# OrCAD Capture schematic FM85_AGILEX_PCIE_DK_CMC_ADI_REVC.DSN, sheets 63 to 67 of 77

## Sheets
63 PWR -VCC_HSSI_GXR: size C
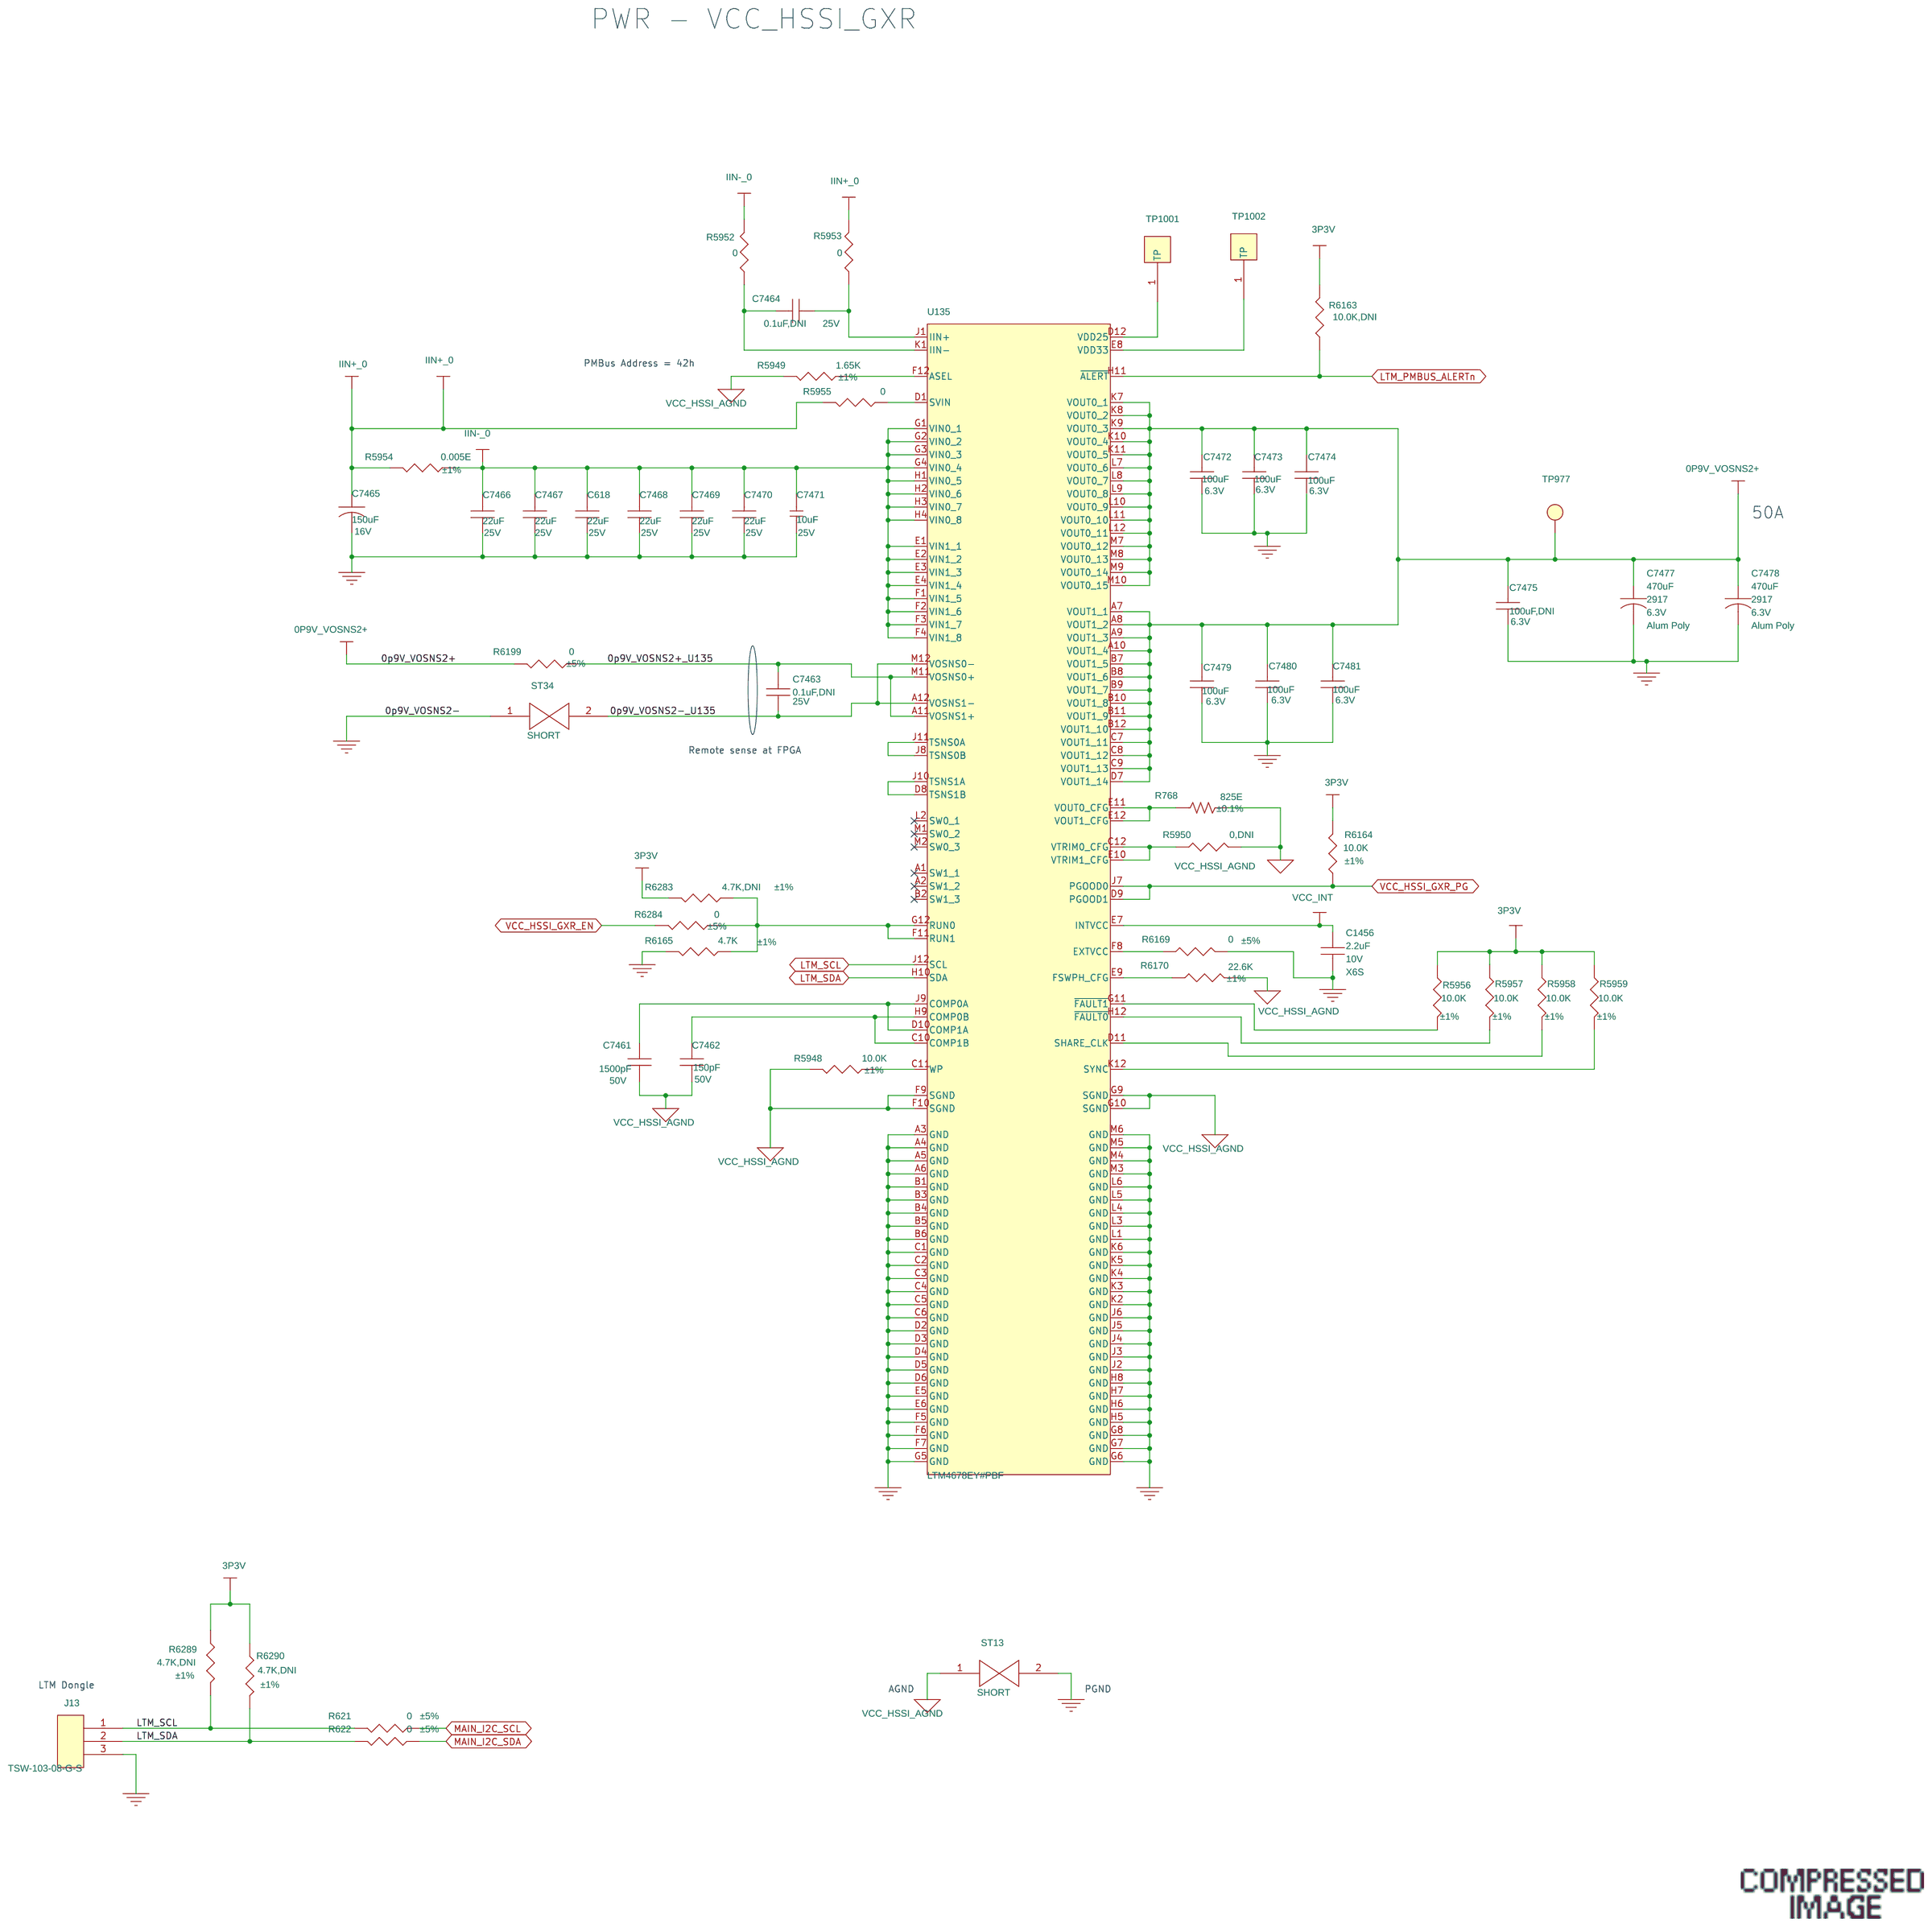
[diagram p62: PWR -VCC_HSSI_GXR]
64 PWR -VCCH: size B
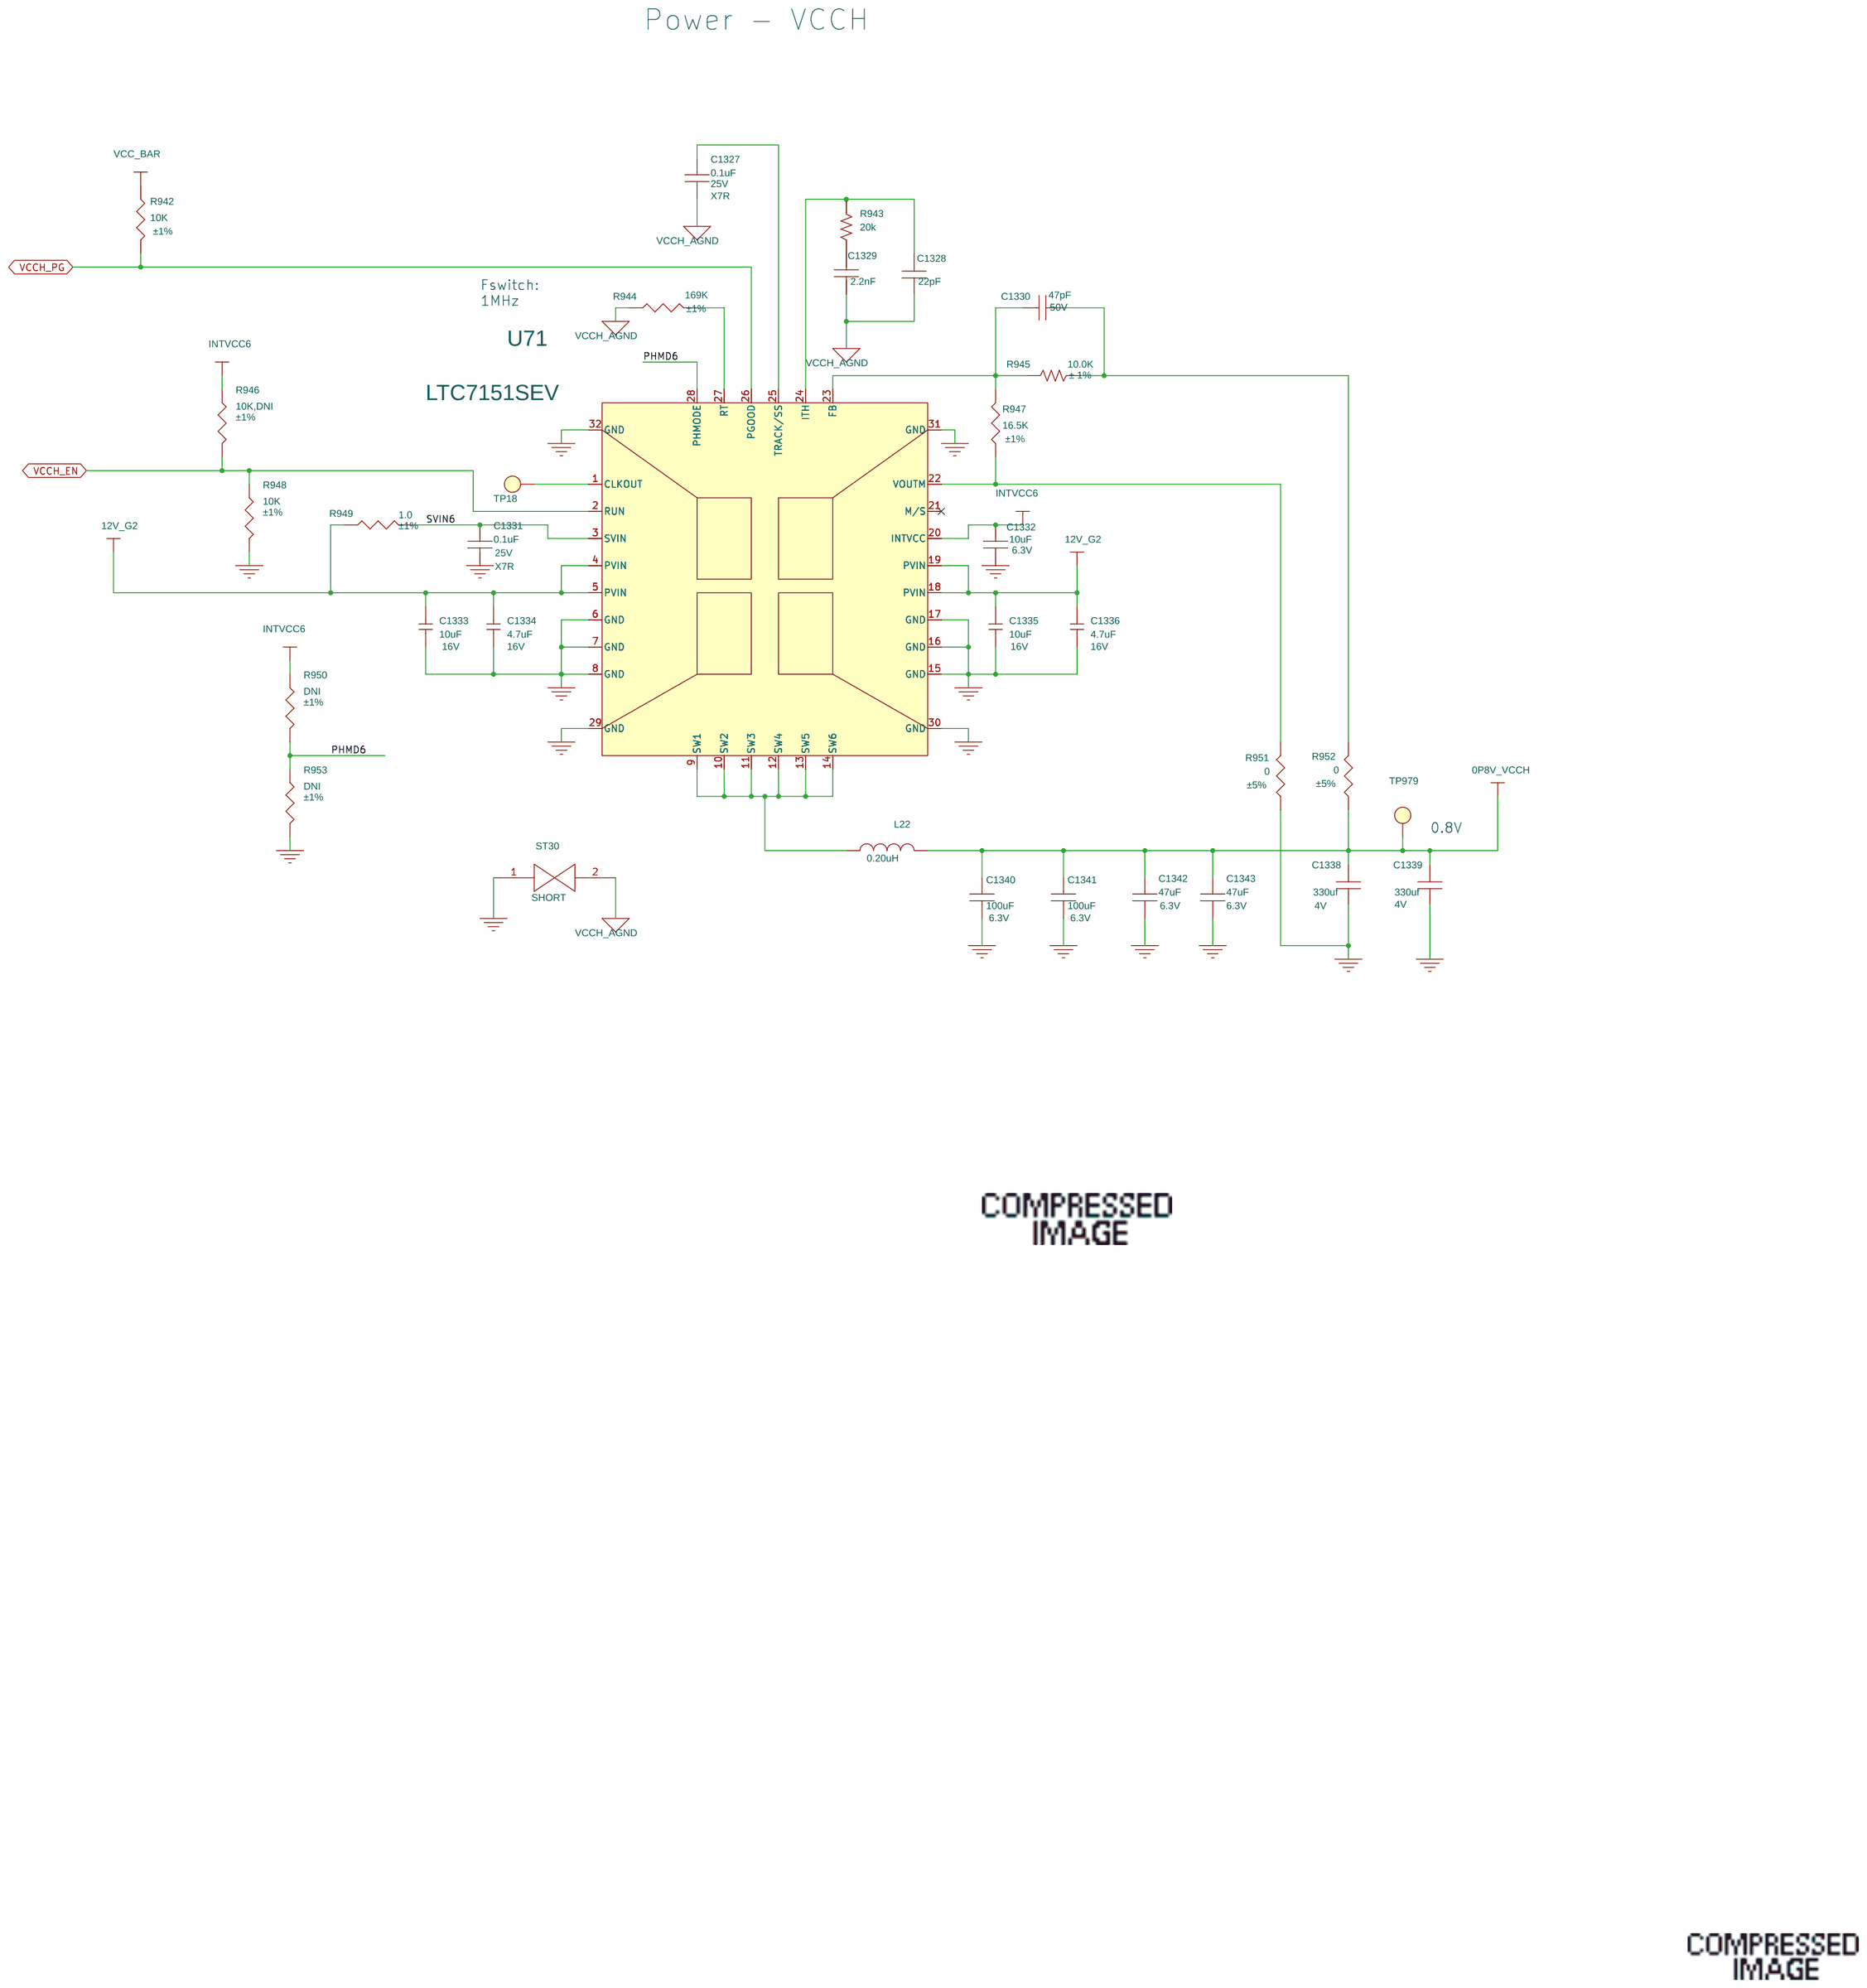
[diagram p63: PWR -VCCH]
65 PWR -VCC_HSSI_GXF: size C
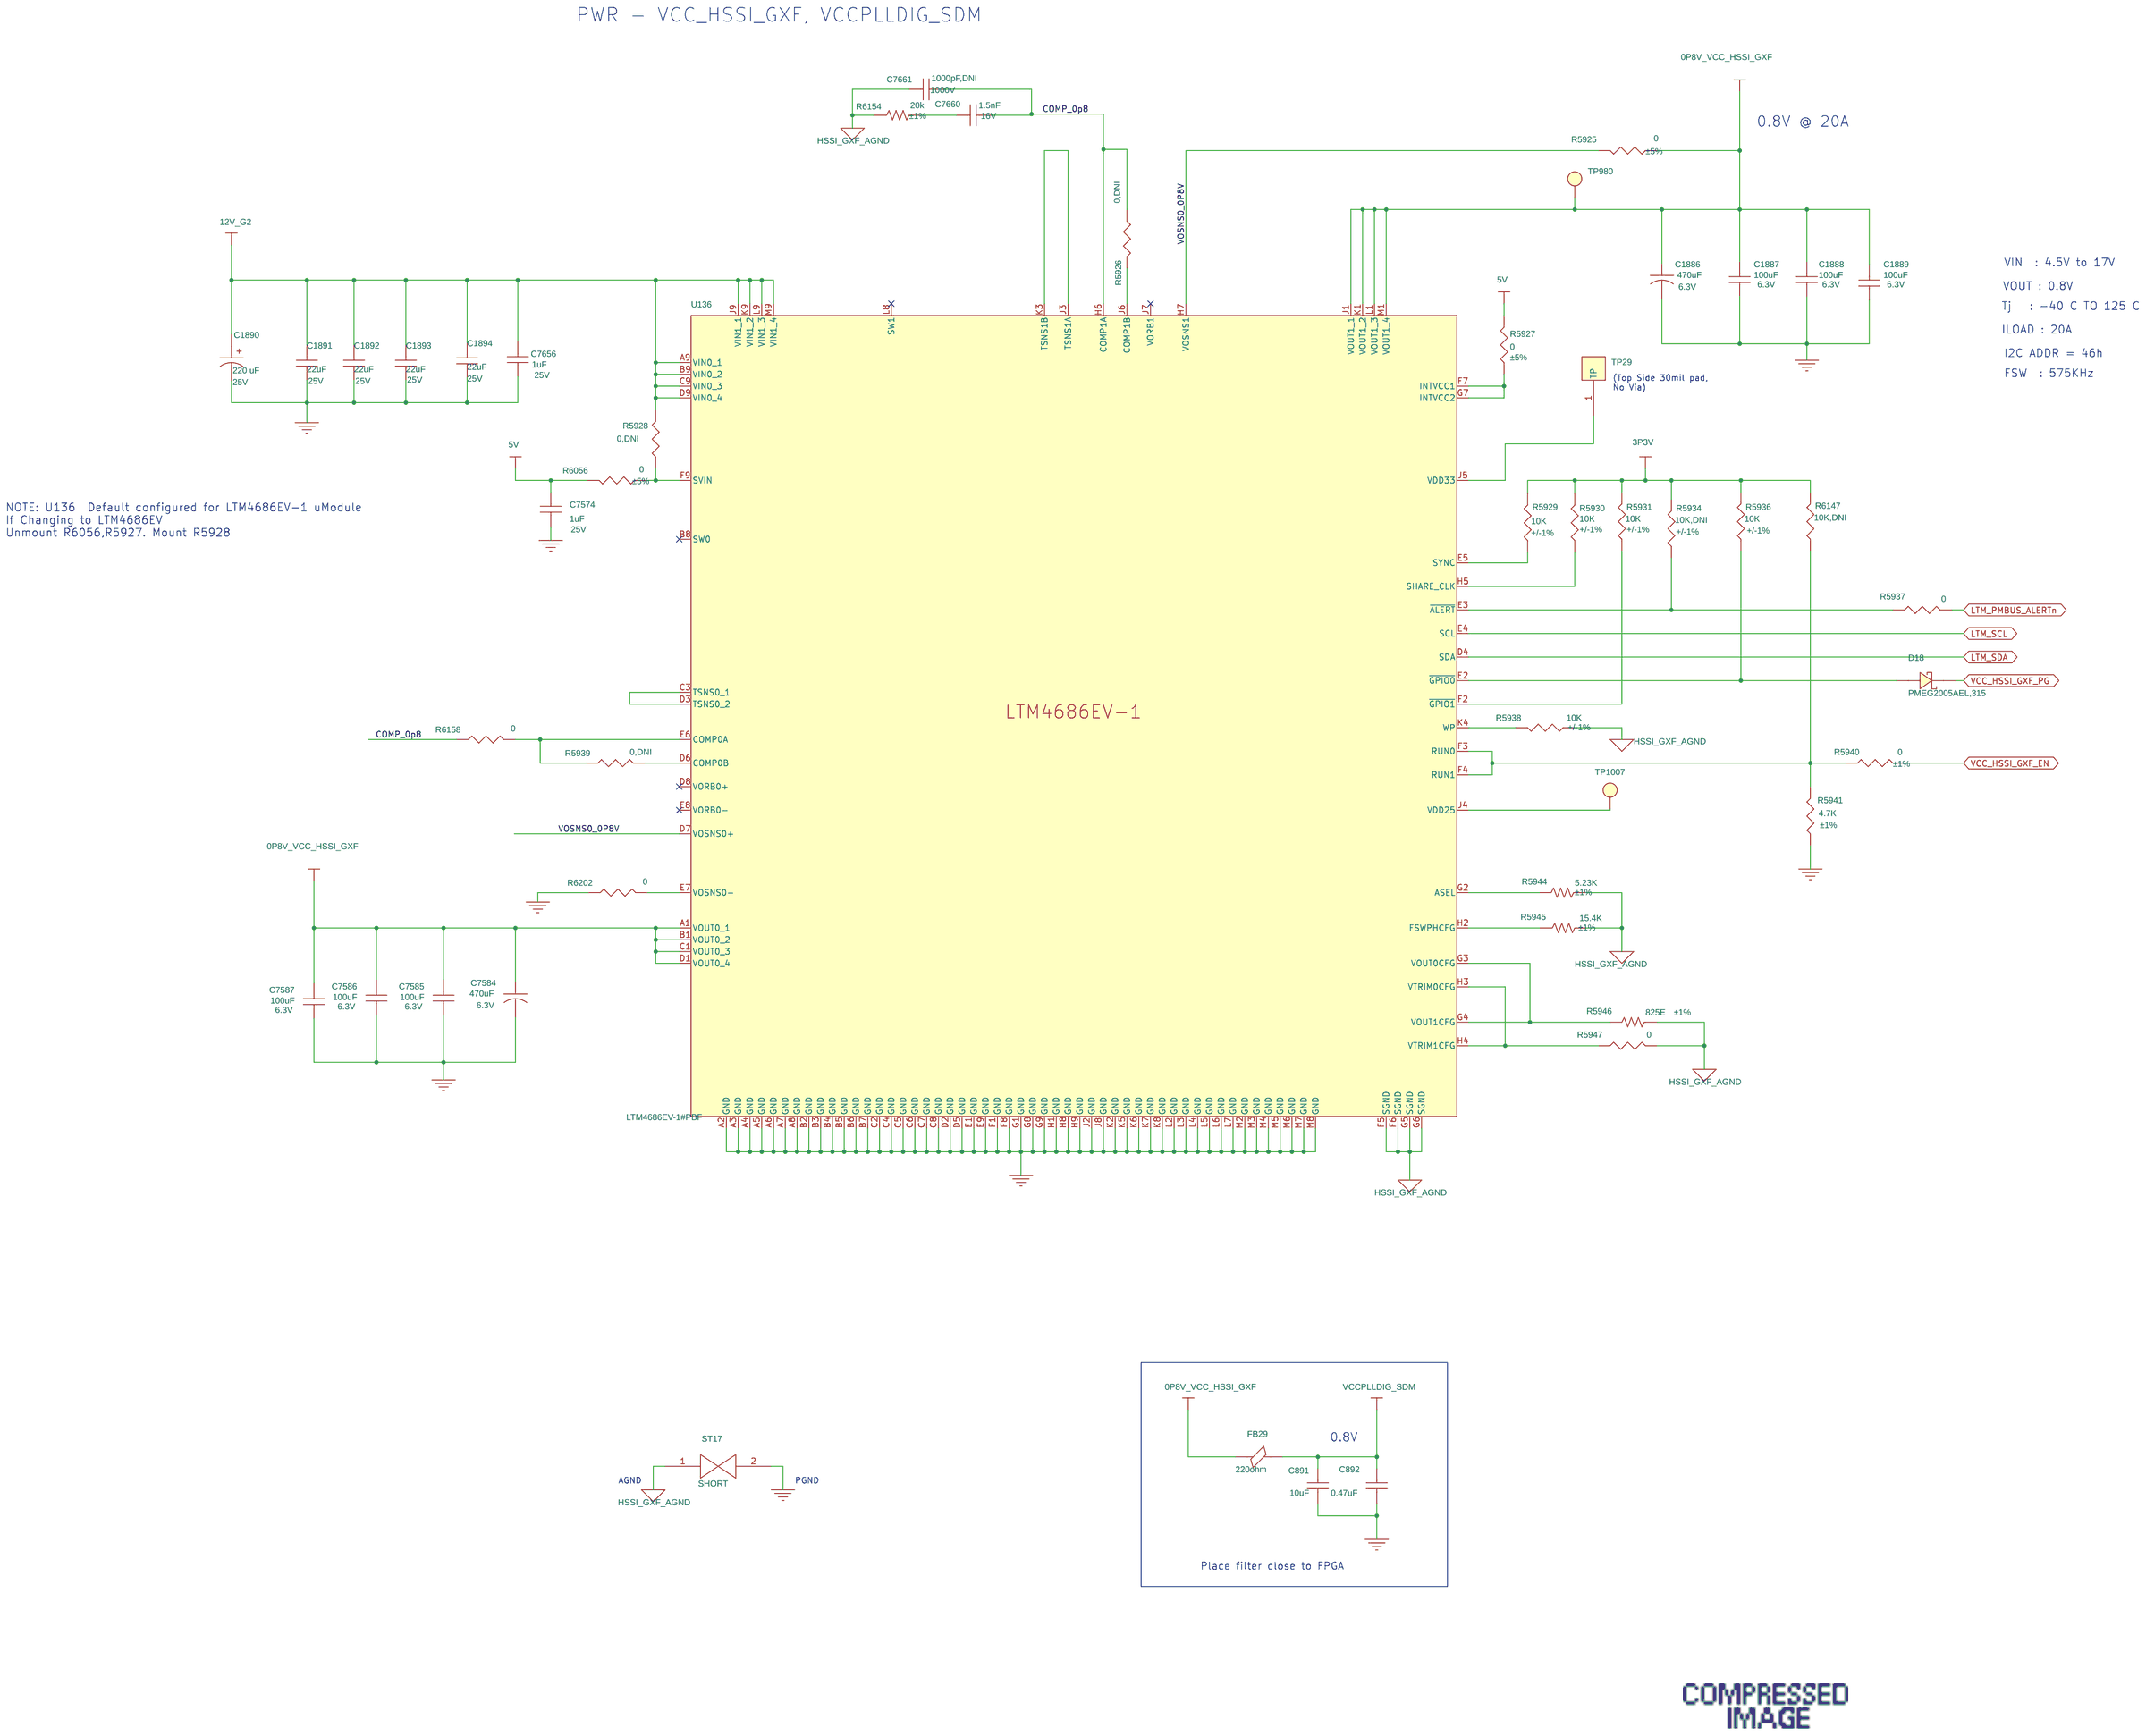
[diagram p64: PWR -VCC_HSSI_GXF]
66 PWR -1p8V: size B
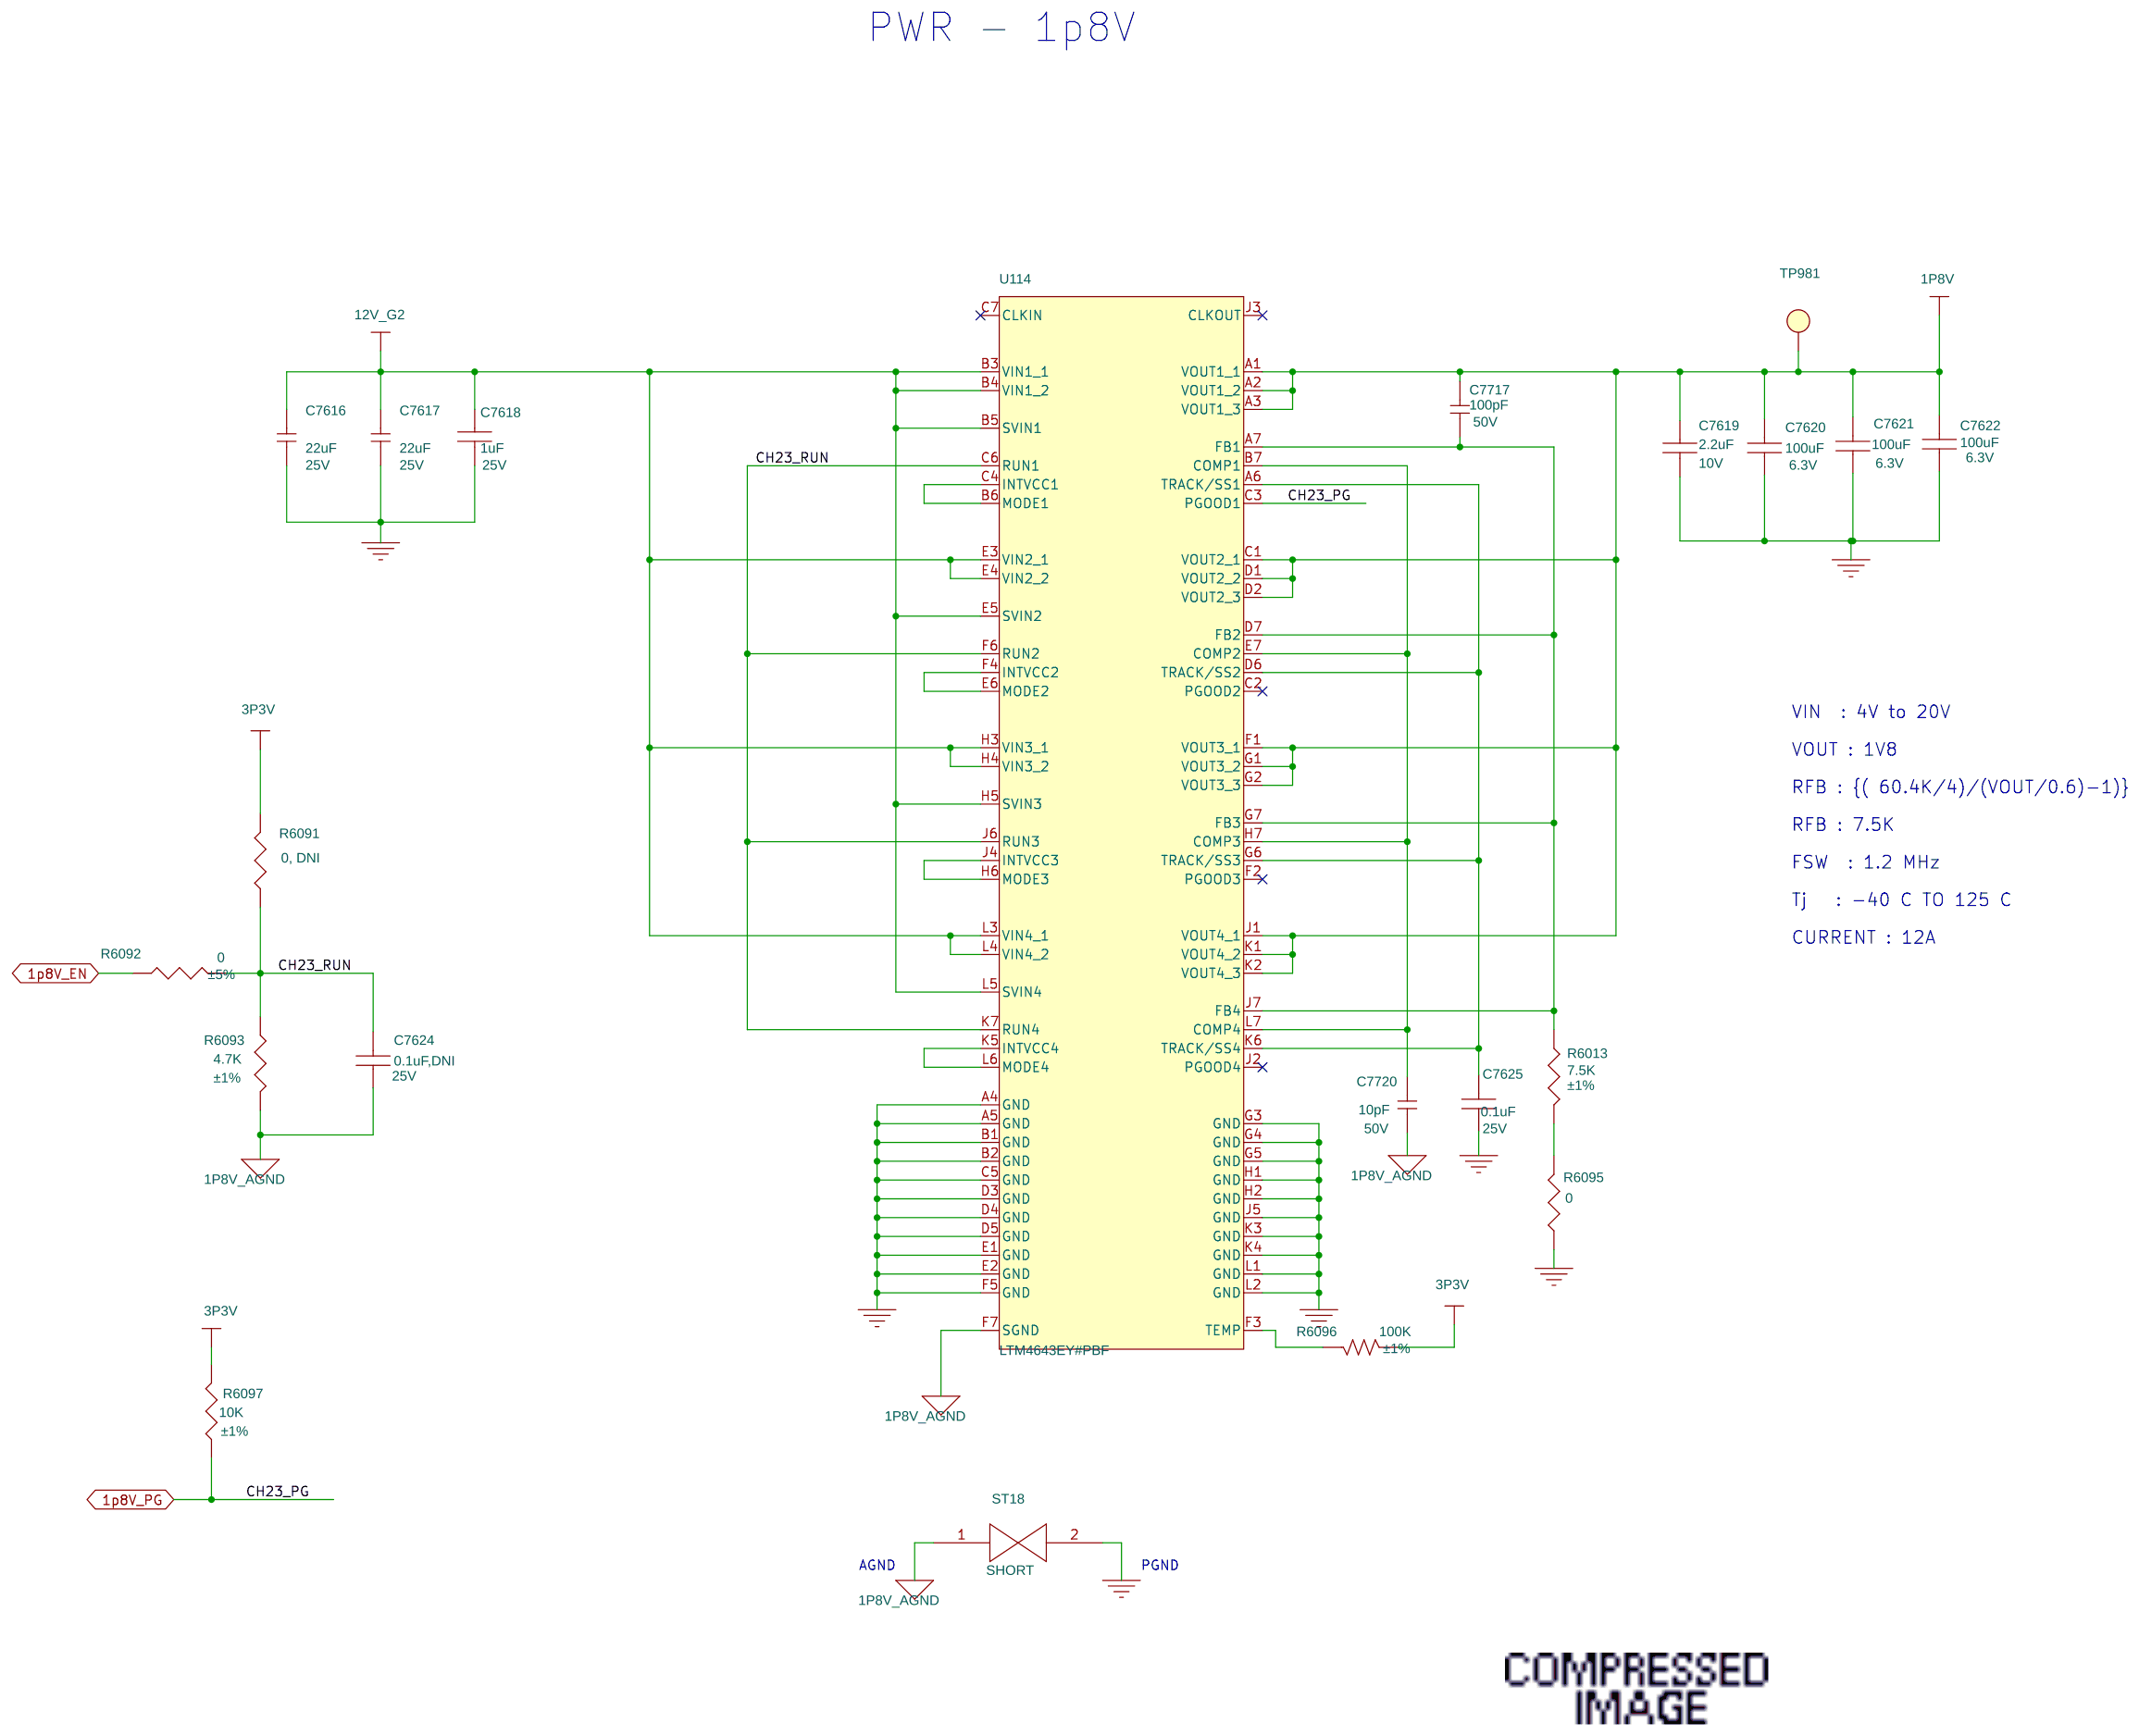
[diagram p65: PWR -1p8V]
67 PWR - IO_1p8V_OK: size B
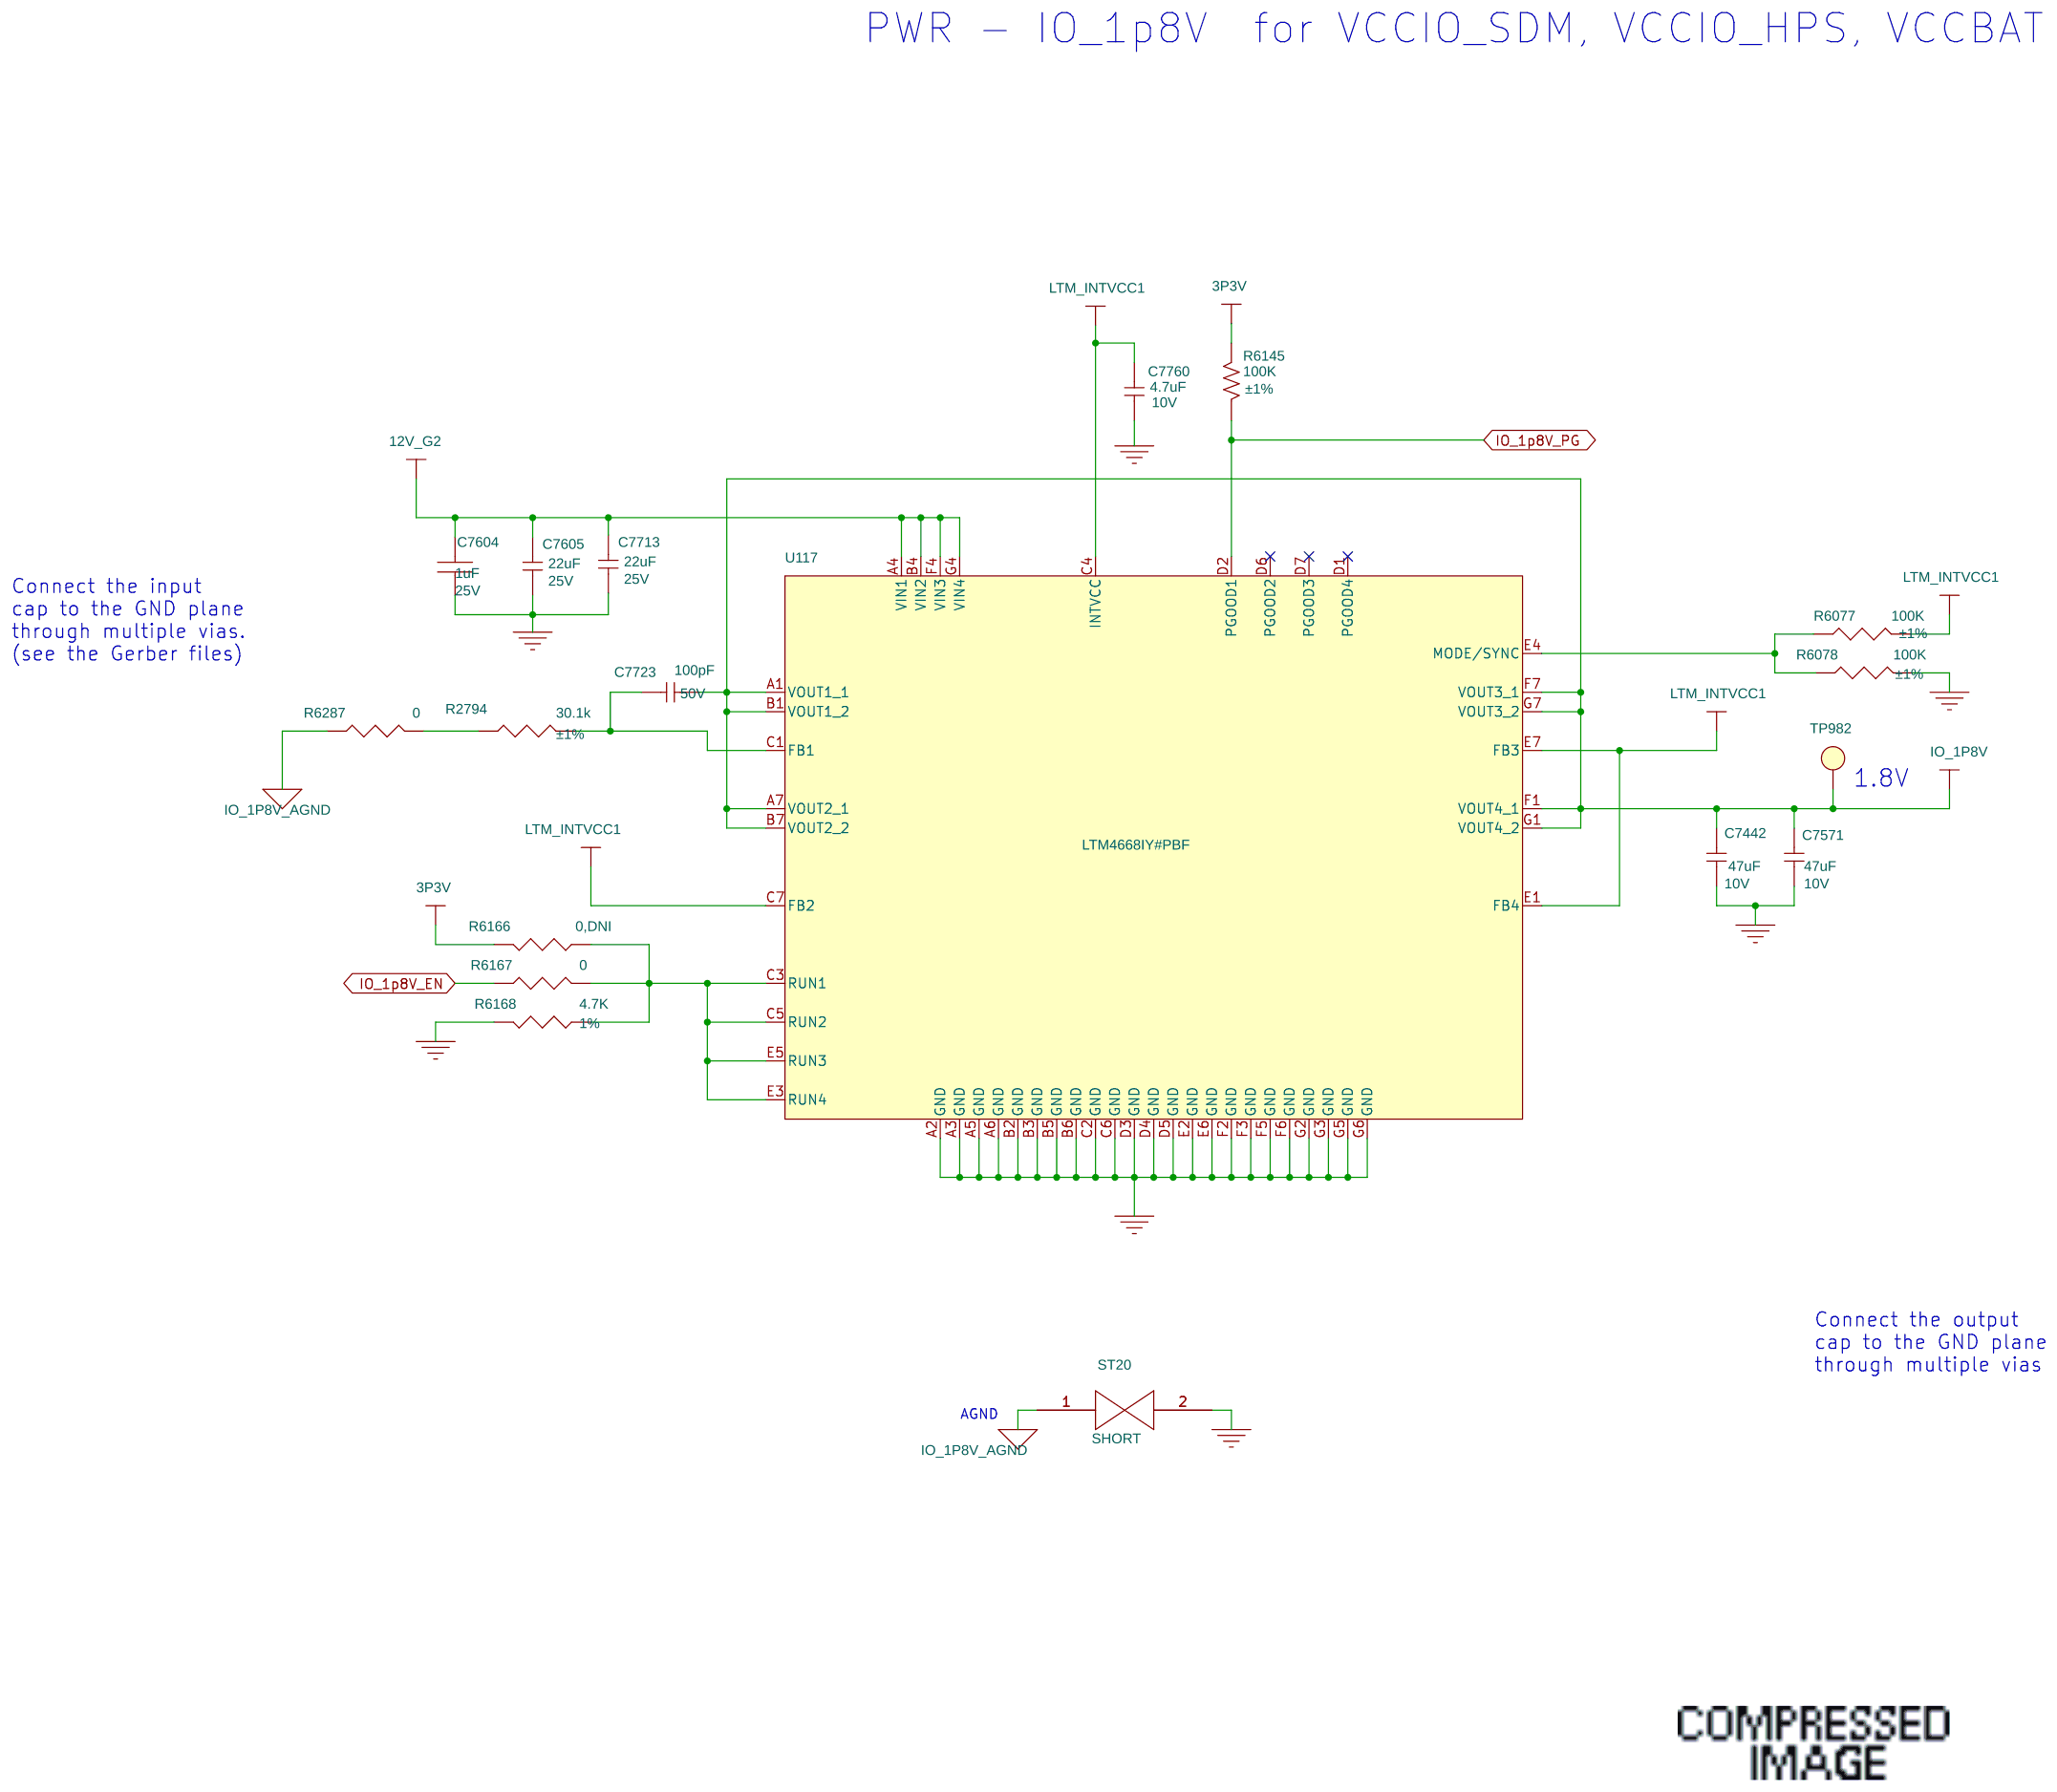
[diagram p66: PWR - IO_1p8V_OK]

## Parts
sheet PWR -1p8V
C7616  22uF  [1206]
C7617  22uF  [1206]
C7618  1uF  [0402]
C7619  2.2uF  [0603]
C7620  100uF  [1206]
C7621  100uF  [1206]
C7622  100uF  [1206]
C7624  0.1uF,DNI  [0402]
C7625  0.1uF  [0402]
C7717  100pF  [0402]
C7720  10pF  [0402]
R6013  7.5K  [0402]
R6091  0, DNI  [0402]
R6092  0  [0402]
R6093  4.7K  [0402]
R6095  0  [0402]
R6096  100K  [R0402]
R6097  10K  [0402]
ST18  SHORT  [SHORT]
TP981  TESTPOINT  [30MIL_TP]
U114  LTM4643EY#PBF  [BGA77C127P7X11_900X1500X262N]
sheet PWR - IO_1p8V_OK
C7442  47uF  [C1206]
C7571  47uF  [C1206]
C7604  1uF  [0402]
C7605  22uF  [1206]
C7713  22uF  [1206]
C7723  100pF  [0402]
C7760  4.7uF  [0402]
R2794  30.1k  [0402]
R6077  100K  [0402]
R6078  100K  [0402]
R6145  100K  [R0402]
R6166  0,DNI  [0402]
R6167  0  [0402]
R6168  4.7K  [0402]
R6287  0  [0402]
ST20  SHORT  [SHORT]
TP982  TESTPOINT  [30MIL_TP]
U117  LTM4668IY#PBF  [BGA49C80P7X7_625X625X230N]
sheet PWR -VCC_HSSI_GXF
C891  10uF  [0603]
C892  0.47uF  [0402]
C1886  470uF  [D2E]
C1887  100uF  [1206]
C1888  100uF  [1206]
C1889  100uF  [1206]
C1890  220 uF  [CT7361-20]
C1891  22uF  [1206]
C1892  22uF  [1206]
C1893  22uF  [1206]
C1894  22uF  [1206]
C7574  1uF  [0402]
C7584  470uF  [D2E]
C7585  100uF  [1206]
C7586  100uF  [1206]
C7587  100uF  [1206]
C7656  1uF  [0402]
C7660  1.5nF  [0402]
C7661  1000pF,DNI  [1206]
D18  PMEG2005AEL,315  [DIO_SOD882]
FB29  220ohm  [0402]
R5925  0  [0402]
R5926  0,DNI  [0402]
R5927  0  [0402]
R5928  0,DNI  [0402]
R5929  10K  [0402]
R5930  10K  [0402]
R5931  10K  [0402]
R5934  10K,DNI  [0402]
R5936  10K  [0402]
R5937  0  [0402]
R5938  10K  [0402]
R5939  0,DNI  [0402]
R5940  0  [0402]
R5941  4.7K  [0402]
R5944  5.23K  [0402]
R5945  15.4K  [0402]
R5946  825E  [0402]
R5947  0  [0402]
R6056  0  [0402]
R6147  10K,DNI  [0402]
R6154  20k  [0402]
R6158  0  [0402]
R6202  0  [0402]
ST17  SHORT  [SHORT]
TP29  TESTPOINT  [30mil_TP]
TP980  TESTPOINT  [30MIL_TP]
TP1007  TESTPOINT  [30MIL_TP]
U136  LTM4686EV-1#PBF  [LGA108C127P9X12_1190X1600X192N]
sheet PWR -VCC_HSSI_GXR
C618  22uF  [1206]
C1456  2.2uF  [0402]
C7461  1500pF  [0402]
C7462  150pF  [0402]
C7463  0.1uF,DNI  [0402]
C7464  0.1uF,DNI  [0402]
C7465  150uF  [7343P_H2MM]
C7466  22uF  [1206]
C7467  22uF  [1206]
C7468  22uF  [1206]
C7469  22uF  [1206]
C7470  22uF  [1206]
C7471  10uF  [1206]
C7472  100uF  [1206]
C7473  100uF  [1206]
C7474  100uF  [1206]
C7475  100uF,DNI  [1206]
C7477  470uF  [2917]
C7478  470uF  [2917]
C7479  100uF  [1206]
C7480  100uF  [1206]
C7481  100uF  [1206]
J13  TSW-103-08-G-S  [1x3_HDR_TH]
R621  0  [0402]
R622  0  [0402]
R768  825E  [0402]
R5948  10.0K  [0402]
R5949  1.65K  [0402]
R5950  0,DNI  [0402]
R5952  0  [0402]
R5953  0  [0402]
R5954  0.005E  [RES_CSNL2512_0_005-0_006]
R5955  0  [0402]
R5956  10.0K  [0402]
R5957  10.0K  [0402]
R5958  10.0K  [0402]
R5959  10.0K  [0402]
R6163  10.0K,DNI  [0402]
R6164  10.0K  [0402]
R6165  4.7K  [0402]
R6169  0  [0402]
R6170  22.6K  [0402]
R6199  0  [0402]
R6283  4.7K,DNI  [0402]
R6284  0  [0402]
R6289  4.7K,DNI  [0402]
R6290  4.7K,DNI  [0402]
ST13  SHORT  [SHORT]
ST34  SHORT  [SHORT]
TP977  TESTPOINT  [30MIL_TP]
TP1001  TESTPOINT  [30mil_TP]
TP1002  TESTPOINT  [30mil_TP]
U135  LTM4678EY#PBF  [BGA144C127P12X12_1600X1600X626]
sheet PWR -VCCH
C1327  0.1uF  [0402]
C1328  22pF  [0603]
C1329  2.2nF  [0402]
C1330  47pF  [0402]
C1331  0.1uF  [0402]
C1332  10uF  [0402]
C1333  10uF  [0805]
C1334  4.7uF  [0603]
C1335  10uF  [0805]
C1336  4.7uF  [0603]
C1338  330uf  [1210]
C1339  330uf  [1210]
C1340  100uF  [0805]
C1341  100uF  [0805]
C1342  47uF  [0603]
C1343  47uF  [0603]
L22  0.20uH  [XEL4030-201ME]
R942  10K  [0402]
R943  20k  [0402]
R944  169K  [0402]
R945  10.0K  [0402]
R946  10K,DNI  [0402]
R947  16.5K  [0402]
R948  10K  [0402]
R949  1.0  [0402]
R950  DNI  [0402]
R951  0  [0402]
R952  0  [0402]
R953  DNI  [0402]
ST30  SHORT  [SHORT]
TP18  TESTPOINT  [30MIL_TP]
TP979  TESTPOINT  [30MIL_TP]
U71  LTC7151SEV  [LQFN_28_5MMX4MM]

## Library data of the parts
C7616 C7617 = Cap,_NP,_1206: CAP - CER, 22UF, 25V, 10%, X5R, 1206; Item Num: K28232-001; Manufacturer: Murata; Manufacturer Part Num: GRM31CR61E226KE15L; RATED_VOLTAGE: 25V
C7618 = CAP: CAP - CER, 1UF, 25V, 10%, X5R, 0402; Item Num: H29050-001; Lead Free Status: Yes; Manufacturer: TDK; Manufacturer Part Num: CGB2A1X5R1E105K033BC; Num Pins: 2; Part Class: CAPACITORS; RATED_VOLTAGE: 25V; RoHS Compliant: Yes
C7619 = CAP: CAP C, 0603, 2.2uF 6.3V, X5R; CLASS: DISCRETE; FPLIST: CC0603N,CC0603L,CC0603M; Inventory Qty: 15202; Item Num: E54182-001; Manufacturer: kemet; Manufacturer PN: C1608X7R1A225M080AC; Manufacturer Part Num: C0603C225K9PAC; PART_NUMBER: 150-3503; RATED_VOLTAGE: 10V; Rated Voltage: 10V; Tolerance: 20%
C1887-C1889 C7472-C7474 C7479-C7481 C7585-C7587 C7620-C7622 = CAP: CAP CER 100UF 6.3V X6T 1206; AGILE_LINK: http://sj-agile9app/Agile/PLMServlet?action=OpenEmailObject&classid=10000&objid=257560276; Item Num: H65271-004; LIFECYCLE_PHASE: Active; Lead Free Status: Lead Free; MFR_LIFECYCLE: Active; Manufacturer: Murata; Manufacturer Part Num: GRM31CD80J107ME39L; Num Pins: 2; PART_SUBCLASS: CAPACITORS; RATED_VOLTAGE: 6.3V; RoHS Compliant: RoHS Compliant; TOLERANCE: 20%; Temperature Coefficient: X6T
C7463 C7464 C7624 = CAP: CAP CER 0.1UF 25V X6S 0402; CAPACITANCE: 0.1uF; Dielectric: X6S; Item Num: K19434-001; LIFECYCLE_PHASE: Active; Lead Free Status: Lead Free; Manufacturer: Murata; Manufacturer Part Num: GRM155C81E104KA12D; Num Pins: 2; Part Class: CAPACITORS; RATED_VOLTAGE: 25V; RoHS Compliant: RoHS Compliant; Tolerance: 10%
C7625 = CAP: CAP CER 0.1UF 25V X6S 0402; Dielectric: X6S; Item Num: K19434-001; LIFECYCLE_PHASE: Active; Lead Free Status: Lead Free; Manufacturer: Murata; Manufacturer Part Num: GRM155C81E104KA12D; Num Pins: 2; Part Class: CAPACITORS; RATED_VOLTAGE: 25V; RoHS Compliant: RoHS Compliant; Tolerance: 10%
C7717 C7723 = Cap,_NP,_0402: CAP, CERAMIC, 100pF, 0402, 5%, 50VDC, NPO; Item Num: A36095-026; Manufacturer: Murata; Manufacturer Part Num: GRM1555C1H101JZ01D; RATED_VOLTAGE: 50V
C7720 = Cap,_NP,_0402: CAP,0402,10PF,50V,5%; Item Num: C17122-001; Manufacturer: KEMET; Manufacturer Part Num: C0402C100J5GACTU; RATED_VOLTAGE: 50V
R6013 = RESISTOR: RES_D,0402,7.5kOHM,1.00%,1/16W; AGILE_LINK: http://sj-agile9app/Agile/PLMServlet?action=OpenEmailObject&classid=10000&objid=146548997; Item Num: G64084-095; LIFECYCLE_PHASE: Active; Lead Free Status: No; MFR_LIFECYCLE: Active; Manufacturer: YAGEO CORP.; Manufacturer Part Num: AC0402FR-077K5L; Num Pins: 2; PART_SUBCLASS: RESISTORS; POWER: 1/16W; RESISTANCE: 10.0K; RoHS Compliant: Yes; TOLERANCE: ±1%
R6091 = RESISTOR: RES ZERO OHM 1/16W 5% 0402 SMD; Altera Part No.: P02-14020R; Item Num: H30887-001; Lead Free Status: No; Manufacturer: Panasonic; Manufacturer Part Num: ERJ-2GE0R00X; Num Pins: 2; Part Class: RESISTORS; Price: 0; RoHS Compliant: Yes; Tolerance: 5%
R6092 R6095 = RESISTOR: RES ZERO OHM 1/16W 5% 0402 SMD; Item Num: H30887-001; Lead Free Status: No; Manufacturer: Panasonic; Manufacturer Part Num: ERJ-2GE0R00X; Num Pins: 2; Part Class: RESISTORS; RoHS Compliant: Yes; Tolerance: ±5%
R6093 R6165 R6283 R6289 R6290 = RESISTOR: RES,4.70K OHMS,1.0%,1/16W,0402; Item Num: D60468-001; Lead Free Status: No; Manufacturer: Panasonic; Manufacturer Part Num: CRCW04024K70FKED; Manufacturer's Part No.: ERJ-2GEJ472X; Num Pins: 2; Part Class: RESISTORS; Price: 0; RoHS Compliant: Yes; TOLERANCE: ±1%
R6096 R6145 = Resistor,_0402: RES, 100K OHMS, 1.0%, 1/10W, 0402; Item Num: E86804-001; Manufacturer: Panasonic; Manufacturer Part Num: ERJ-2RKF1003X; TOLERANCE: ±1%
R6097 = RESISTOR: RES,10.0K OHMS,1.0%,1/16W, 0402; AGILE_LINK: http://sj-agile9app/Agile/PLMServlet?action=OpenEmailObject&classid=10000&objid=146548997; Item Num: A93548-034; LIFECYCLE_PHASE: Active; Lead Free Status: No; MFR_LIFECYCLE: Active; Manufacturer: Panasonic; Manufacturer Part Num: ERJ-2RKF1002X; Num Pins: 2; PART_SUBCLASS: RESISTORS; POWER: 1/16W; RESISTANCE: 10.0K; RoHS Compliant: Yes; TOLERANCE: ±1%
ST13 ST17 ST18 ST20 ST30 ST34 = SHORT
TP18 TP977 TP979-TP982 TP1007 = TP,_0.016_,_Thru_Hole
U114 = LTM4643EY#PBF: IC, ULTRATHIN QUAD uMODULE REGULATOR, WITH CONFIGURABLE 3A OUTPUT ARRAY, BGA-77P, SMD; Item Num: M75351-001
C7442 C7571 = Cap,_NP,_1206: CAP - CER 47UF 10V 20% X5R 1206; Item Num: K13655-001; Manufacturer: TDK Electronics; Manufacturer Part Num: C3216X5R1A476M160AB; RATED_VOLTAGE: 10V
C7604 = CAP: CAPC,X6S,0402,1.00UF,25.00V,+/- 10%; IPN: xxxxxx-xxx; Item Num: H81594-001; Lead Free Status: Yes; Manufacturer: Murata; Manufacturer Part Num: GRM155C81E105KE11D; Num Pins: 2; Part Class: CAPACITORS; RATED_VOLTAGE: 25V; RoHS Compliant: Yes; Temperature Coefficient: X6S; Voltage: 25V
C7605 C7713 = Cap,_NP,_1206: CAP - CER, 22UF, 25V, 10%, X5R, 1206; Agile Part Number: 06593; Dielectric: X5R/X6S; Item Num: K28232-001; Manufacturer: Murata Electronics; Manufacturer Part Num: GRM31CR61E226KE15L; Package: 0805; RATED_VOLTAGE: 25V; Structure: MLCC
C7760 = Cap,_NP,_0402: CAP CER 4.7UF 10V X5R 0402; Agile Part Number: P03-17662R; Dielectric: X5R; Item Num: J89506-001; Manufacturer: MURATA; Manufacturer Part Num: ZRB15XR61A475KE01D; Part Number: C1005X5R1A475K050BE; RATED_VOLTAGE: 10V; TOLERANCE: ±10%; Voltage: 10V
R2794 = RESISTOR: RES_D,0402,30.1kOHM,1.00%,1/16W; Item Num: G21796-018; Lead Free Status: No; Manufacturer: YAGEO CORP.; Manufacturer Part Num: RC0402FR-0730K1P; Manufacturer's Part No.: RC0402FR-0730K1P; Num Pins: 2; Part Class: RESISTORS; Price: 0; RoHS Compliant: Yes; TOLERANCE: ±1%
R6077 R6078 = RESISTOR: RES,100K OHMS,1.0%,1/16W,0402; Item Num: A78422-001; Lead Free Status: No; Manufacturer: Panasonic; Manufacturer Part Num: ERJ-2RKF1003X; Num Pins: 2; Part Class: Resistors; Price: 0; RoHS Compliant: Yes; TOLERANCE: ±1%
R6166 = RESISTOR: RES D,0402,0.00 OHM,5.00%,1/16W; Altera Part No.: P02-14020R; Item Num: A93549-001; Lead Free Status: No; Manufacturer: YAGEO CORP.; Manufacturer Part Num: RC0402JR-070RL; Num Pins: 2; Part Class: RESISTORS; Price: 0; RoHS Compliant: Yes; Tolerance: ±5%
R6167 R6287 = RESISTOR: RES D,0402,0.00 OHM,5.00%,1/16W; Altera Part No.: P02-14020R; Item Num: A93549-001; LIFECYCLE_PHASE: Active; Lead Free Status: No; MFR_LIFECYCLE: Active; Manufacturer: YAGEO CORP.; Manufacturer Part Num: RC0402JR-070RL; Num Pins: 2; PART_SUBCLASS: RESISTORS; POWER: 1/16W; Part Class: RESISTORS; RoHS Compliant: RoHS Compliant; Tolerance: ±5%
R6168 = RESISTOR: RES,4.70K OHMS,1.0%,1/16W,0402; Item Num: D60468-001; Lead Free Status: No; Manufacturer: Vishay; Manufacturer Part Num: CRCW04024K70FKED; Manufacturer's Part No.: ERJ-2GEJ472X; Num Pins: 2; Part Class: RESISTORS; Price: 0; RoHS Compliant: Yes; TOLERANCE: 1%
U117 = LTM4668IY#PBF: IC, DC/DC uMODULE REGULATOR, QUAD, 1.5A, BGA-49P; Item Num: M85055-001
C891 = CAP: CAP 10UF 10VDC X5R +/-15% 0603; Item Num: J60031-001; Lead Free Status: No; Manufacturer: Murata; Manufacturer Part Num: GRM188R61A106KE69D; Num Pins: 2; Part Class: Capacitors; Price: 0; RoHS Compliant: Yes
C892 = CAP: CAP - CER, .47UF, 10V, X5R, 0402; AGILE_LINK: http://sj-agile9app/Agile/PLMServlet?action=OpenEmailObject&classid=10000&objid=256989651; Item Num: H75789-001; LIFECYCLE_PHASE: Active; Lead Free Status: Lead Free; MFR_LIFECYCLE: Active; Manufacturer: Murata; Manufacturer Part Num: GRM155R61A474KE15D; Num Pins: 2; PART_SUBCLASS: CAPACITORS; Part Class: CAPACITORS; RATED_VOLTAGE: 10V; RoHS Compliant: RoHS Compliant; Tolerance: +80%/-20%
C1886 C7584 = PCAP: CAP TANT POLY 470UF 6.3V 2917; ESR: 10mOHM; Item Num: D96354-001; LIFECYCLE_PHASE: Active; Lead Free Status: Lead Free; MFR_LIFECYCLE: Active; Manufacturer: Panasonic; Manufacturer Part Num: 6TPF470MAH; Num Pins: 2; PART_SUBCLASS: CAPACITORS; RATED_VOLTAGE: 6.3V; RoHS Compliant: RoHS Compliant; Working Voltage: 6.3V
C1890 = T523H227M025APE070: CAP, TANT, 220 uF, 20%, 25V, 7361-20, SMD; Item Num: M76712-001; MANUFACTURER: KYOCERA; Manufacture Part Number: TCN4227M025R0100; Manufacturer Part Num: TCN4227M025R0100; PART_NUMBER: TCN4227M025R0100; RATED_VOLTAGE: 25V
C1891-C1894 = CAP: CAP - CER, 22UF, 25V, 10%, X5R, 1206; Agile Part Number: P03-17640R; Item Num: K28232-001; Lead Free Status: Yes; Manufacturer: Murata; Manufacturer Part Num: GRM31CR61E226KE15L; Num Pins: 2; Part Class: Capacitors; Price: 0; RATED_VOLTAGE: 25V; RoHS Compliant: Yes
C7574 = CAP: CAPC,X6S,0402,1.00UF,25.00V,+/- 10%; Item Num: H81594-001; Lead Free Status: Yes; Manufacturer: Murata; Manufacturer Part Num: GRM155C81E105KE11D; Num Pins: 2; Part Class: CAPACITORS; RATED_VOLTAGE: 25V; RoHS Compliant: Yes; Temperature Coefficient: X6S; Voltage: 25V
C7656 = CAP: CAP - CER, 1UF, 25V, 10%, X5R, 0402; Item Num: H29050-001; Lead Free Status: Yes; Manufacturer: TDK Electronics; Manufacturer Part Num: CGB2A1X5R1E105K033BC; Num Pins: 2; Part Class: CAPACITORS; RATED_VOLTAGE: 25V; RoHS Compliant: Yes
C7660 = CAP: CAPC,X7R,0402,1.5NF,16.00V,+/- 10%; Dielectric: X6S; Item Num: A31095-023; LIFECYCLE_PHASE: Active; Lead Free Status: Lead Free; Manufacturer: TDK CORPORATION OF AMERICA; Manufacturer Part Num: C1005X7R1H152KTB09N; Num Pins: 2; Part Class: CAPACITORS; RATED_VOLTAGE: 16V; RoHS Compliant: RoHS Compliant; Tolerance: +/- 10%
C7661 = CAP: CAP CER 1000PF 1000V X7R 1206; AGILE_LINK: http://sj-agile9app/Agile/PLMServlet?action=OpenEmailObject&classid=10000&objid=215384813; CAPACITANCE: 1000pF; Item Num: K13749-001; LIFECYCLE_PHASE: Active; Lead Free Status: Lead Free; MFR_LIFECYCLE: Active; Manufacturer: Murata; Manufacturer Part Num: GRM31BR73A102KW01L; Num Pins: 2; PACKAGING: Tape & Reel (TR); PART_SUBCLASS: CAPACITORS; RATED_VOLTAGE: 1000V; RoHS Compliant: RoHS Compliant; Supplier Part Num: GRM31BR73A102KW01L; Tolerance: +/-10%
D18 = PMEG2005AEL,315: Item Num: H64664-001; Manufacturer Part Num: PMEG2005AEL
FB29 = BEAD_FERRITE_SM: FER-BEAD,0402,220.0OHM,580.0MA,+/-25%; Imax (A): 600mA; Item Num: A51464-023; Manufacturer: Murata Electronics; Manufacturer Part Num: BLM15AX221SN1D; Rdc (Ohms): 350mOhm; Tolerance (%): 25%
R5925 R5927 = RESISTOR: RES D,0402,0.00 OHM,5.00%,1/16W; Altera Part No.: P02-14020R; Item Num: A93549-001; Lead Free Status: No; Manufacturer: Panasonic; Manufacturer Part Num: ERJ-2GE0R00X; Num Pins: 2; Part Class: RESISTORS; RoHS Compliant: Yes; Tolerance: ±5%
R5926 R5928 R5939 = RESISTOR: RES D,0402,0.00 OHM,5.00%,1/16W; Altera Part No.: P02-14020R; Item Num: A93549-001; Lead Free Status: No; Manufacturer: Panasonic; Manufacturer Part Num: ERJ-2GE0R00X; Num Pins: 2; Part Class: RESISTORS; Price: 0; RoHS Compliant: Yes; Tolerance: 5%
R5929-R5931 R5934 R5936 R5938 R6147 = RESISTOR: RES,10.0K OHMS,1.0%,1/16W, 0402; AGILE_LINK: http://sj-agile9app/Agile/PLMServlet?action=OpenEmailObject&classid=10000&objid=146548997; Item Num: A93548-034; LIFECYCLE_PHASE: Active; Lead Free Status: No; MFR_LIFECYCLE: Active; Manufacturer: Panasonic; Manufacturer Part Num: ERJ-2RKF1002X; Num Pins: 2; PART_SUBCLASS: RESISTORS; POWER: 1/16W; RESISTANCE: 10.0K; RoHS Compliant: Yes; TOLERANCE: +/-1%
R5937 R5940 R5947 R6202 = RESISTOR: RES D,0402,0.00 OHM,5.00%,1/16W; Altera Part No.: P02-14020R; Item Num: A93549-001; Lead Free Status: No; Manufacturer: Panasonic; Manufacturer Part Num: ERJ-2GE0R00X; Num Pins: 2; Part Class: RESISTORS; RoHS Compliant: Yes; Tolerance: ±1%
R5941 = RESISTOR: RES,4.70K OHMS,1.0%,1/16W,0402; IPN: xxxxxx-xxx; Item Num: A93548-517; Lead Free Status: No; Manufacturer: Vishay; Manufacturer Part Num: CRCW04024K70FKED; Manufacturer's Part No.: ERJ-2GEJ472X; Num Pins: 2; Part Class: RESISTORS; Price: 0; RoHS Compliant: Yes; TOLERANCE: ±1%
R5944 = Resistor,_0402: RES 5.23K OHM 1% 1/16W 0402; Item Num: G21796-141; Manufacturer: YAGEO CORP.Walsin Technology Corporation; Manufacturer Part Num: WR04X5231FTL; Part Number: WR04X5231FTL; TOLERANCE: ±1%
R5945 = Resistor,_0402: RES_D,0402,15.4kOHM,1.00%,1/16W; Item Num: G21796-108; Manufacturer: WALSIN TECHNOLOGY CORP; Manufacturer Part Num: RC0402FR-0715K4P; Part Number: RC0402FR-0715K4P; Power: 1/16W; TOLERANCE: ±1%
R5946 = Resistor,_0402: RES_D,0402,825OHM,0.1%,1/16W; Item Num: M79107-001; Manufacturer: PANASONIC; Manufacturer Part Num: ERA-2AEB8250X; Part Number: ERA-2AEB8250X; TOLERANCE: ±1%
R6056 = RESISTOR: RES D,0402,0.00 OHM,5.00%,1/16W; Altera Part No.: P02-14020R; Item Num: A93549-001; Lead Free Status: No; Manufacturer: Panasonic; Manufacturer Part Num: ERJ-2GE0R00X; Num Pins: 2; Part Class: RESISTORS; RoHS Compliant: Yes; Tolerance: 5%; Tolerance (%): ±5%
R943 R6154 = Resistor,_0402: RES 20.0K ohm, 1/16W 1% 0402 SMD; Agile Part Number: P02-15647R; Item Num: A93548-181; Manufacturer: Yageo; Manufacturer Part Num: RC0402FR-0720KL; Power: 1/16W; TOLERANCE: ±1%
R6158 = RESISTOR: RES D,0402,0.00 OHM,5.00%,1/16W; Altera Part No.: P02-14020R; Item Num: A93549-001; Lead Free Status: No; Manufacturer: Panasonic; Manufacturer Part Num: ERJ-2GE0R00X; Num Pins: 2; Part Class: RESISTORS; RoHS Compliant: Yes; Tolerance: 5%
TP29 TP1001 TP1002 = TESTPOINT
U136 = LTM4686EV-1#PBF: Item Num: M75350-001
C618 C7466-C7470 = CAP: CAP - CER, 22UF, 25V, 10%, X5R, 1206; Item Num: K28232-001; Lead Free Status: Yes; Manufacturer: Murata; Manufacturer Part Num: GRM31CR61E226KE15L; Num Pins: 2; Part Class: Capacitors; Price: 0; RATED_VOLTAGE: 25V; RoHS Compliant: Yes
C1456 = CAP: CAP CER 2.2UF 10V X6S 0402; CAPACITANCE: 0.1uF; Dielectric: X6S; Item Num: H90637-001; LIFECYCLE_PHASE: Active; Lead Free Status: Lead Free; Manufacturer: Murata; Manufacturer Part Num: GRM155C81A225KE44D; Num Pins: 2; Part Class: CAPACITORS; RATED_VOLTAGE: 10V; RoHS Compliant: RoHS Compliant; Tolerance: 10%
C7461 = CAP: MWG,CAP,XR7,0402,1500PF,50V,10%,YES; CAPACITANCE: 0.1uF; Dielectric: X6S; Item Num: H57680-001 / K13738-001; LIFECYCLE_PHASE: Active; Lead Free Status: Lead Free; Manufacturer: MURATA ELEC. NORTH AMERICA; Manufacturer Part Num: GRM155R71H152KA01D; Num Pins: 2; Part Class: CAPACITORS; RATED_VOLTAGE: 50V; RoHS Compliant: RoHS Compliant; Tolerance: 10%
C7462 = CAP: CAPC,NP0,0402,150PF,25V,+/- 5%; CAPACITANCE: 0.1uF; Dielectric: X6S; Item Num: K28252-001; LIFECYCLE_PHASE: Active; Lead Free Status: Lead Free; Manufacturer: MURATA ELEC. NORTH AMERICA; Manufacturer Part Num: GRM1555C1E151JA01D; Num Pins: 2; Part Class: CAPACITORS; RATED_VOLTAGE: 50V; RoHS Compliant: RoHS Compliant; Tolerance: +/-5%
C7465 = PCAP: CAPS,TA-P,D20,150.00uF,16.00V,+/- 20%,D20; Item Num: H97831-001; LIFECYCLE_PHASE: Active; Lead Free Status: Lead Free; MFR_LIFECYCLE: Active; Manufacturer: Panasonic; Manufacturer Part Num: 1CTQC15173F1; Num Pins: 2; PART_SUBCLASS: CAPACITORS; RATED_VOLTAGE: 16V; RoHS Compliant: RoHS Compliant; TOLERANCE: +/-20%
C7471 = Cap,_NP,_1206: CAP - CERAMIC, 10UF, 10%, X5R, 25V, 1206; Agile Part Number: P03-15063R; Dielectric: X7R; Item Num: K28255-001; Manufacturer: TDK; Manufacturer Part Num: C3216X7R1E106K160AB; Part Number: C3216X7R1E106K160AB; RATED_VOLTAGE: 25V; TOLERANCE: ±10%; Voltage: 25V
C7475 = CAP: CAP CER 100UF 6.3V X6T 1206; AGILE_LINK: http://sj-agile9app/Agile/PLMServlet?action=OpenEmailObject&classid=10000&objid=257560276; CAPACITANCE: 100uF; Item Num: H65271-004; LIFECYCLE_PHASE: Active; Lead Free Status: Lead Free; MFR_LIFECYCLE: Active; Manufacturer: Murata; Manufacturer Part Num: GRM31CD80J107ME39L; Num Pins: 2; PART_SUBCLASS: CAPACITORS; RATED_VOLTAGE: 6.3V; RoHS Compliant: RoHS Compliant; TOLERANCE: 20%; Temperature Coefficient: X6T
C7477 = PCAP: CAPS,AL-P,V,470.00uF,6.3V,+/- 20%,V,; AGILE_LINK: http://sj-agile9app/Agile/PLMServlet?action=OpenEmailObject&classid=10000&objid=257237054; Item Num: C22068-001; LIFECYCLE_PHASE: Active; Lead Free Status: Lead Free; MFR_LIFECYCLE: Active; Manufacturer: Panasonic; Manufacturer Part Num: EEFGX0E471R; Num Pins: 2; PART_SUBCLASS: CAPACITORS; RATED_VOLTAGE: 6.3V; RoHS Compliant: RoHS Compliant; TOLERANCE: 20%; Type: Alum Poly
C7478 = PCAP: CAPS,AL-P,V,470.00uF,6.3V,+/- 20%,V,; AGILE_LINK: http://sj-agile9app/Agile/PLMServlet?action=OpenEmailObject&classid=10000&objid=257237054; Item Num: C22068-001; LIFECYCLE_PHASE: Active; Lead Free Status: Lead Free; MFR_LIFECYCLE: Active; Manufacturer: Panasonic; Manufacturer Part Num: EEF-GX0E471R; Num Pins: 2; PART_SUBCLASS: CAPACITORS; RATED_VOLTAGE: 6.3V; RoHS Compliant: RoHS Compliant; TOLERANCE: 20%; Type: Alum Poly
J13 = 1x3_HDR_TH: 1X3 .100"CENTER HEADER, .145" MIN SOLDER TAIL; Item Num: K12462-001; Manufacturer: Samtec
R621 R622 R6199 = RES_0_OHM_5%_1_16W_0402_SMD: Item Num: H30887-001; Tolerance (%): ±5%
R768 = Resistor,_0402: RES_D,0402,825OHM,0.1%,1/16W; Item Num: M79107-001; Manufacturer: PANASONIC; Manufacturer Part Num: ERA-2AEB8250X; Part Number: ERA-2AEB8250X; Power: 1/16W; TOLERANCE: ±0.1%
R5948 R5956-R5959 = RESISTOR: RES,10.0K OHMS,1.0%,1/16W, 0402; AGILE_LINK: http://sj-agile9app/Agile/PLMServlet?action=OpenEmailObject&classid=10000&objid=146548997; Item Num: K28115-001; LIFECYCLE_PHASE: Active; Lead Free Status: No; MFR_LIFECYCLE: Active; Manufacturer: Panasonic; Manufacturer Part Num: ERJ-2RKF1002X; Num Pins: 2; PART_SUBCLASS: RESISTORS; POWER: 1/16W; RoHS Compliant: Yes; TOLERANCE: ±1%
R5949 = RES_0_OHM_5%_1_16W_0402_SMD: RES_D,0402,1.65kOHM,1.00%,1/16W; Item Num: G21796-164; Manufacturer: WALSIN TECHNOLOGY CORP; Manufacturer Part Num: WR04X1651FTR; TOLERANCE: ±1%
R5950 = RESISTOR: RES ZERO OHM 1/16W 5% 0402 SMD; Altera Part No.: P02-14020R; Item Num: H30887-001; Lead Free Status: No; Manufacturer: Panasonic; Manufacturer Part Num: ERJ-2GE0R00X; Num Pins: 2; Part Class: RESISTORS; Price: 0; RoHS Compliant: Yes; Tolerance: ±5%
R5952 R5953 = RES_0_OHM_5%_1_16W_0402_SMD: Item Num: H30887-001; Tolerance: 5%
R5954 = RES_0_OHM_5%_1_16W_0402_SMD: RES 0.005 OHM 1% 2W 2512; Item Num: M85067-001; Manufacturer Part Num: CSNL2512FT5L00; Tolerance (%): ±1%
R5955 = RES_0_OHM_5%_1_16W_0402_SMD: Item Num: H30887-001; Tolerance: ±5%
R6163 = RESISTOR: RES,10.0K OHMS,1.0%,1/16W, 0402; AGILE_LINK: http://sj-agile9app/Agile/PLMServlet?action=OpenEmailObject&classid=10000&objid=146548997; Item Num: K28115-001; LIFECYCLE_PHASE: Active; Lead Free Status: No; MFR_LIFECYCLE: Active; Manufacturer: Panasonic; Manufacturer Part Num: ERJ-2RKF1002X; Num Pins: 2; PART_SUBCLASS: RESISTORS; POWER: 1/16W; RESISTANCE: 10K; RoHS Compliant: Yes; TOLERANCE: 1%
R6164 = RESISTOR: RES,10.0K OHMS,1.0%,1/16W, 0402; AGILE_LINK: http://sj-agile9app/Agile/PLMServlet?action=OpenEmailObject&classid=10000&objid=146548997; Item Num: K28115-001; LIFECYCLE_PHASE: Active; Lead Free Status: No; MFR_LIFECYCLE: Active; Manufacturer: Panasonic; Manufacturer Part Num: ERJ-2RKF1002X; Num Pins: 2; PART_SUBCLASS: RESISTORS; POWER: 1/16W; RESISTANCE: 10K; RoHS Compliant: Yes; TOLERANCE: ±1%
R6169 = RESISTOR: RES ZERO OHM 1/16W 5% 0402 SMD; Altera Part No.: P02-14020R; Item Num: H30887-001; Lead Free Status: No; Manufacturer: Panasonic; Manufacturer Part Num: ERJ-2GE0R00X; Num Pins: 2; Part Class: RESISTORS; RoHS Compliant: Yes; Tolerance: ±5%
R6170 = RESISTOR: RES_D,0402,22.6kOHM,1.00%,1/16W; Item Num: G21796-022; Lead Free Status: No; Manufacturer: YAGEO CORP.; Manufacturer Part Num: RC0402FR-0722K6P; Num Pins: 2; Part Class: Resistors; TOLERANCE: ±1%
R6284 = RES_0_OHM_5%_1_16W_0402_SMD: Item Num: H30887-001; TOLERANCE: ±5%
U135 = LTM4678EY#PBF: Item Num: K80928-001
C1327 C1331 = CAP: CAP CER 0.1UF 25V 20% X7R 0402; Dielectric: X7R; Item Num: A36096-112; LIFECYCLE_PHASE: Active; Lead Free Status: Lead Free; Manufacturer: Murata; Manufacturer Part Num: GRM155R71E104KE14D; Num Pins: 2; Part Class: CAPACITORS; RATED_VOLTAGE: 25V; RoHS Compliant: RoHS Compliant; Tolerance: 10%
C1328 = CAP_NP: CAPC,C0G,0603,22.000PF,50.000V,+/- 5%,; Item Num: M23241-001; Manufacturer: Murata; Manufacturer Part Num: GRM1885C1H220JA01J; RATED_VOLTAGE: 50V
C1329 = CAP: CAP CER 2200PF 50V 10% X7R 0402; AGILE_LINK: http://sj-agile9app/Agile/PLMServlet?action=OpenEmailObject&classid=10000&objid=204246494; CAPACITANCE: 2200pF; Item Num: A36096-022; LIFECYCLE_PHASE: Active; Manufacturer: Murata; Manufacturer Part Num: GRM155R71H222KA01D; Num Pins: 2; PART_SUBCLASS: CAPACITORS; RATED_VOLTAGE: 50V; TOLERANCE: +/-10%
C1330 = CAP: CAP,0402,47PF,50V,DC,5%; Item Num: G64756-001; Manufacturer: Panasonic; Manufacturer Part Num: ECJ-0EC1H470J; RATED_VOLTAGE: 50V
C1332 = CAP: CAP CER 10UF 6.3V X5R 0402; Item Num: K46607-001; Lead Free Status: Lead Free; Manufacturer: Murata Electronics North America; Manufacturer Part Num: GRJ155R60J106ME11D; Num Pins: 2; PART_SUBCLASS: CAPACITORS; Part Class: CAPACITORS; RATED_VOLTAGE: 6.3V; RoHS Compliant: RoHS Compliant; Temperature Coefficient: X5R
C1333 C1335 = Cap,_NP,_1206: CAP - CERAMIC, 10UF, 10%, X5R, 16V, 0805; Dielectric: X5R; Item Num: K68729-001; Manufacturer: Yageo; Manufacturer Part Num: CC0805KKX5R7BB106; Part Number: CC0805KKX5R7BB106; RATED_VOLTAGE: 16V; TOLERANCE: ±10%; Voltage: 16V
C1334 C1336 = Cap,_NP,_1206: CAPC,X5R,0603,4.7UF,16.00V,+/- 10%; Agile Part Number: P03-15063R; Dielectric: X5R; Item Num: 602433-099; Manufacturer: Murata; Manufacturer Part Num: GRM188R61C475KAAJD; Part Number: GRM188R61C475KAAJD; RATED_VOLTAGE: 16V; TOLERANCE: ±10%; Voltage: 16V
C1338 = CAP: CAPC,X5R,1210,330.000UF,4.000V,+/- 20%; Dielectric: X5R; Item Num: 644066-175; Manufacturer: Murata; Manufacturer PN: GRM32ER60G337ME05L; Manufacturer Part Num: GRM32ER60G337ME05L; RATED_VOLTAGE: 4V; RoHS Compliant: Yes; Tolerance: 20%; Working Voltage: 4V
C1339 = CAP: CAPC,X5R,1210,330.000UF,4.000V,+/- 20%; Dielectric: X5R; IPN: xxxxxx-xxx; Item Num: 644066-175; Manufacturer: Murata; Manufacturer PN: GRM32ER60G337ME05L; Manufacturer Part Num: GRM32ER60G337ME05L; RATED_VOLTAGE: 4V; RoHS Compliant: Yes; Tolerance: 20%; Working Voltage: 4V
C1340 C1341 = CAP: CAP CER 100UF 6.3V X5R 0805; Item Num: K32109-001; Lead Free Status: Lead Free; Manufacturer: Murata Electronics North America; Manufacturer Part Num: GRM21BR60J107ME15L; Num Pins: 2; PART_SUBCLASS: CAPACITORS; Part Class: CAPACITORS; RATED_VOLTAGE: 6.3V; RoHS Compliant: RoHS Compliant; Temperature Coefficient: X5R
C1342 C1343 = CAP: CAP CER 47UF 6.3V X5R 0603; Item Num: K31624-001; MFR_LIFECYCLE: Active; Manufacturer: Murata Electronics North America; Manufacturer Part Num: GRM188R60J476ME15D; Num Pins: 2; PART_SUBCLASS: CAPACITORS; RATED_VOLTAGE: 6.3V; RoHS Compliant: RoHS Compliant; TOLERANCE: 20%
L22 = Inductor,_Discrete: FIXED INDUCTORS 0.20UH 22A,; Item Num: M29834-001; Manufacturer: Coil Craft; Package: 3740
R942 R948 = RESISTOR: RES,10.0K OHMS,1.0%,1/16W, 0402; AGILE_LINK: http://sj-agile9app/Agile/PLMServlet?action=OpenEmailObject&classid=10000&objid=146548997; Item Num: A93548-034; LIFECYCLE_PHASE: Active; Lead Free Status: No; MFR_LIFECYCLE: Active; Manufacturer: Panasonic; Manufacturer Part Num: ERJ-2RKF1002X; Num Pins: 2; PART_SUBCLASS: RESISTORS; POWER: 1/16W; RoHS Compliant: Yes; TOLERANCE: ±1%
R944 = RESISTOR: RES - 169K OHM, 1/16W, 1%, 0402 SMD; Item Num: A93548-290; Lead Free Status: No; Manufacturer: Yageo; Manufacturer Part Num: RC0402FR-07169KL; Num Pins: 2; Part Class: RESISTORS; Price: 0; RoHS Compliant: Yes; Tolerance: ±1%
R945 = Resistor,_0402: RES,10.0K OHMS,1.0%,1/16W, 0402; Agile Part Number: P02-17688R; Item Num: K28115-001; Manufacturer: Panasonic; Manufacturer Part Num: ERJ-2RKF1002X; Part Number: ERJ-2RKF1002X; Power: 1/16W; TOLERANCE: ± 1%
R946 R950 R953 = RESISTOR: RES,10.0K OHMS,1.0%,1/16W, 0402; AGILE_LINK: http://sj-agile9app/Agile/PLMServlet?action=OpenEmailObject&classid=10000&objid=146548997; Item Num: A93548-034; LIFECYCLE_PHASE: Active; Lead Free Status: No; MFR_LIFECYCLE: Active; Manufacturer: Panasonic; Manufacturer Part Num: ERJ-2RKF1002X; Num Pins: 2; PART_SUBCLASS: RESISTORS; POWER: 1/16W; RESISTANCE: 10K; RoHS Compliant: Yes; TOLERANCE: ±1%
R947 = RESISTOR: RES_D,0402,16.5kOHM,1.00%,1/16W,; AGILE_LINK: http://sj-agile9app/Agile/PLMServlet?action=OpenEmailObject&classid=10000&objid=146548997; Item Num: G21796-036; LIFECYCLE_PHASE: Active; Lead Free Status: No; MFR_LIFECYCLE: Active; Manufacturer: Yageo; Manufacturer Part Num: RC0402FR-0716K5P; Num Pins: 2; PART_SUBCLASS: RESISTORS; POWER: 1/16W; RoHS Compliant: Yes; TOLERANCE: ±1%
R949 = RESISTOR: RES,1.0 OHMS,1.0%,1/16W, 0402; AGILE_LINK: http://sj-agile9app/Agile/PLMServlet?action=OpenEmailObject&classid=10000&objid=146548997; Item Num: A93548-210; LIFECYCLE_PHASE: Active; Lead Free Status: No; MFR_LIFECYCLE: Active; Manufacturer: Yageo; Manufacturer Part Num: RC0402FR-071RL; Num Pins: 2; PART_SUBCLASS: RESISTORS; POWER: 1/16W; RoHS Compliant: Yes; TOLERANCE: ±1%
R951 R952 = RESISTOR: RES D,0402,0.00 OHM,5.00%,1/16W; Altera Part No.: P02-14020R; Item Num: A93549-001; LIFECYCLE_PHASE: Active; Lead Free Status: No; MFR_LIFECYCLE: Active; Manufacturer: Panasonic; Manufacturer Part Num: ERJ-2GE0R00X; Num Pins: 2; PART_SUBCLASS: RESISTORS; POWER: 1/16W; Part Class: RESISTORS; RoHS Compliant: RoHS Compliant; Tolerance: ±5%
U71 = LTC3543EDCB_0: REGULATOR,20VIN 15A SILENT SW2,15A STEP-DOWN DC/DC; Item Num: M21811-001; Manufacturer: Analog Devices; Manufacturer Part Num: LTC7151SEV#PBF

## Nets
5V: C7574.1 R5927.2 R6056.1 ; also on sheet 48 57 59 68 73
12V_G2: C1333.2 C1334.2 C1335.2 C1336.2 C1890.1 C1891.2 C1892.2 C1893.2 C1894.2 C7465.1 C7604.2 C7605.2 C7616.2 C7617.2 C7618.1 C7656.2 C7713.2 R949.2 R5928.1 R5953.2 R5954.1 R5955.1 U71.4(PVIN) U71.5(PVIN) U71.18(PVIN) U71.19(PVIN) U114.B3(VIN1_1) U114.B4(VIN1_2) U114.B5(SVIN1) U114.E3(VIN2_1) U114.E4(VIN2_2) U114.E5(SVIN2) U114.H3(VIN3_1) U114.H4(VIN3_2) U114.H5(SVIN3) U114.L3(VIN4_1) U114.L4(VIN4_2) U114.L5(SVIN4) U117.A4(VIN1) U117.B4(VIN2) U117.F4(VIN3) U117.G4(VIN4) U136.A9(VIN0_1) U136.B9(VIN0_2) U136.C9(VIN0_3) U136.D9(VIN0_4) U136.J9(VIN1_1) U136.K9(VIN1_2) U136.L9(VIN1_3) U136.M9(VIN1_4) ; also on sheet 53 57 58 59 60 61 62 69 70 71 73
GND: C618.1 C891.2 C892.2 C1331.2 C1332.2 C1333.1 C1334.1 C1335.1 C1336.1 C1338.1 C1339.1 C1340.2 C1341.2 C1342.2 C1343.2 C1456.2 C1886.2 C1887.1 C1888.1 C1889.1 C1890.2 C1891.1 C1892.1 C1893.1 C1894.1 C7442.1 C7465.2 C7466.1 C7467.1 C7468.1 C7469.1 C7470.1 C7471.1 C7472.1 C7473.1 C7474.1 C7475.1 C7477.2 C7478.2 C7479.1 C7480.1 C7481.1 C7571.1 C7574.2 C7584.2 C7585.1 C7586.1 C7587.1 C7604.1 C7605.1 C7616.1 C7617.1 C7618.2 C7619.2 C7620.1 C7621.1 C7622.1 C7625.1 C7656.1 C7713.1 C7760.1 J13.3 R948.1 R951.1 R953.1 R5941.1 R6078.1 R6095.2 R6165.2 R6168.2 R6169.1 R6202.1 ST13.2 ST17.2 ST18.2 ST20.2 ST30.1 ST34.1 U71.6(GND) U71.7(GND) U71.8(GND) U71.15(GND) U71.16(GND) U71.17(GND) U71.29(GND) U71.30(GND) U71.31(GND) U71.32(GND) U114.A4(GND) U114.A5(GND) U114.B1(GND) U114.B2(GND) U114.C5(GND) U114.D3(GND) U114.D4(GND) U114.D5(GND) U114.E1(GND) U114.E2(GND) U114.F5(GND) U114.G3(GND) U114.G4(GND) U114.G5(GND) U114.H1(GND) U114.H2(GND) U114.J5(GND) U114.K3(GND) U114.K4(GND) U114.L1(GND) U114.L2(GND) U117.A2(GND) U117.A3(GND) U117.A5(GND) U117.A6(GND) U117.B2(GND) U117.B3(GND) U117.B5(GND) U117.B6(GND) U117.C2(GND) U117.C6(GND) U117.D3(GND) U117.D4(GND) U117.D5(GND) U117.E2(GND) U117.E6(GND) U117.F2(GND) U117.F3(GND) U117.F5(GND) U117.F6(GND) U117.G2(GND) U117.G3(GND) U117.G5(GND) U117.G6(GND) U135.A3(GND) U135.A4(GND) U135.A5(GND) U135.A6(GND) U135.B1(GND) U135.B3(GND) U135.B4(GND) U135.B5(GND) U135.B6(GND) U135.C1(GND) U135.C2(GND) U135.C3(GND) U135.C4(GND) U135.C5(GND) U135.C6(GND) U135.D2(GND) U135.D3(GND) U135.D4(GND) U135.D5(GND) U135.D6(GND) U135.E5(GND) U135.E6(GND) U135.F5(GND) U135.F6(GND) U135.F7(GND) U135.G5(GND) U135.G6(GND) U135.G7(GND) U135.G8(GND) U135.H5(GND) U135.H6(GND) U135.H7(GND) U135.H8(GND) U135.J2(GND) U135.J3(GND) U135.J4(GND) U135.J5(GND) U135.J6(GND) U135.K2(GND) U135.K3(GND) U135.K4(GND) U135.K5(GND) U135.K6(GND) U135.L1(GND) U135.L3(GND) U135.L4(GND) U135.L5(GND) U135.L6(GND) U135.M3(GND) U135.M4(GND) U135.M5(GND) U135.M6(GND) U136.A2(GND) U136.A3(GND) U136.A4(GND) U136.A5(GND) U136.A6(GND) U136.A7(GND) U136.A8(GND) U136.B2(GND) U136.B3(GND) U136.B4(GND) U136.B5(GND) U136.B6(GND) U136.B7(GND) U136.C2(GND) U136.C4(GND) U136.C5(GND) U136.C6(GND) U136.C7(GND) U136.C8(GND) U136.D2(GND) U136.D5(GND) U136.E1(GND) U136.E9(GND) U136.F1(GND) U136.F8(GND) U136.G1(GND) U136.G8(GND) U136.G9(GND) U136.H1(GND) U136.H8(GND) U136.H9(GND) U136.J2(GND) U136.J8(GND) U136.K2(GND) U136.K5(GND) U136.K6(GND) U136.K7(GND) U136.K8(GND) U136.L2(GND) U136.L3(GND) U136.L4(GND) U136.L5(GND) U136.L6(GND) U136.L7(GND) U136.M2(GND) U136.M3(GND) U136.M4(GND) U136.M5(GND) U136.M6(GND) U136.M7(GND) U136.M8(GND) ; also on sheet 9 10 11 13 14 15 16 17 18 19 20 21 22 23 25 26 27 28 29 30 31 32 33 34 35 36 38 39 40 41 42 43 44 45 46 47 48 49 50 51 52 53 54 55 56 57 58 59 60 61 62 68 69 70 71 72 73 74 75 76 77
SVIN6: C1331.1 R949.1 U71.3(SVIN)
VCC_HSSI_AGND: C7461.2 C7462.2 R768.2 R5948.2 R5949.1 R5950.1 R6170.1 ST13.1 U135.F9(SGND) U135.F10(SGND) U135.G9(SGND) U135.G10(SGND)
VCC_HSSI_GXF_EN: R5940.2 ; also on sheet 51
VCC_HSSI_GXF_PG: D18.1(K) ; also on sheet 49
VCC_HSSI_GXR_EN: R6284.1 ; also on sheet 51
VCC_HSSI_GXR_PG: R6164.2 U135.D9(PGOOD1) U135.J7(PGOOD0) ; also on sheet 49
VCC_INT: C1456.1 U135.E7(INTVCC)
VCCH_AGND: C1327.2 C1328.1 C1329.2 R944.2 ST30.2
VCCH_EN: R946.1 R948.2 U71.2(RUN) ; also on sheet 51
VCCH_PG: R942.1 U71.26(PGOOD) ; also on sheet 50
VCCPLLDIG_SDM: C891.1 C892.1 FB29.2 ; also on sheet 38 76
0p8V_VCC_HSSI_GXF: C1886.1 C1887.2 C1888.2 C1889.2 C7584.1 C7585.2 C7586.2 C7587.2 FB29.1 R5925.1 TP980.1 U136.A1(VOUT0_1) U136.B1(VOUT0_2) U136.C1(VOUT0_3) U136.D1(VOUT0_4) U136.J1(VOUT1_1) U136.K1(VOUT1_2) U136.L1(VOUT1_3) U136.M1(VOUT1_4) ; also on sheet 38 75
0p8V_VCCH: C1338.2 C1339.2 C1340.1 C1341.1 C1342.1 C1343.1 L22.2 R952.1 TP979.1 ; also on sheet 38 75 77
0p9V_VCC_HSSI_GXR: C7472.2 C7473.2 C7474.2 C7475.2 C7477.1 C7478.1 C7479.2 C7480.2 C7481.2 R6199.1 TP977.1 U135.A7(VOUT1_1) U135.A8(VOUT1_2) U135.A9(VOUT1_3) U135.A10(VOUT1_4) U135.B7(VOUT1_5) U135.B8(VOUT1_6) U135.B9(VOUT1_7) U135.B10(VOUT1_8) U135.B11(VOUT1_9) U135.B12(VOUT1_10) U135.C7(VOUT1_11) U135.C8(VOUT1_12) U135.C9(VOUT1_13) U135.D7(VOUT1_14) U135.K7(VOUT0_1) U135.K8(VOUT0_2) U135.K9(VOUT0_3) U135.K10(VOUT0_4) U135.K11(VOUT0_5) U135.L7(VOUT0_6) U135.L8(VOUT0_7) U135.L9(VOUT0_8) U135.L10(VOUT0_9) U135.L11(VOUT0_10) U135.L12(VOUT0_11) U135.M7(VOUT0_12) U135.M8(VOUT0_13) U135.M9(VOUT0_14) U135.M10(VOUT0_15) ; also on sheet 38 75 77
0p9V_VOSNS2+_U135: C7463.2 R6199.2 U135.A11(VOSNS1+) U135.M11(VOSNS0+)
0p9V_VOSNS2-_U135: C7463.1 ST34.2 U135.A12(VOSNS1-) U135.M12(VOSNS0-)
1p8V: C7619.1 C7620.2 C7621.2 C7622.2 C7717.1 TP981.1 U114.A1(VOUT1_1) U114.A2(VOUT1_2) U114.A3(VOUT1_3) U114.C1(VOUT2_1) U114.D1(VOUT2_2) U114.D2(VOUT2_3) U114.F1(VOUT3_1) U114.G1(VOUT3_2) U114.G2(VOUT3_3) U114.J1(VOUT4_1) U114.K1(VOUT4_2) U114.K2(VOUT4_3) ; also on sheet 39 76
1p8V_AGND: C7624.1 C7720.2 R6093.1 ST18.1 U114.F7(SGND)
1p8V_EN: R6092.2 ; also on sheet 51
1p8V_PG: R6097.1 U114.C3(PGOOD1) ; also on sheet 49
3p3V: R5929.2 R5930.2 R5931.2 R5934.2 R5936.2 R5956.1 R5957.1 R5958.1 R5959.1 R6091.2 R6096.2 R6097.2 R6145.2 R6147.2 R6163.1 R6164.1 R6166.2 R6283.2 R6289.1 R6290.1 ; also on sheet 54 58 59 69 70 71 72 73 74
CH23_RUN: C7624.2 R6091.1 R6092.1 R6093.2 U114.C6(RUN1) U114.F6(RUN2) U114.J6(RUN3) U114.K7(RUN4)
COMP_0p8: C7660.2 C7661.2 R5926.1 R6158.1 U136.H6(COMP1A)
HSSI_GXF_AGND: C7661.1 R5938.1 R5944.1 R5945.2 R5946.1 R5947.1 R6154.1 ST17.1 U136.F5(SGND) U136.F6(SGND) U136.G5(SGND) U136.G6(SGND)
IIN-_0: C618.2 C7466.2 C7467.2 C7468.2 C7469.2 C7470.2 C7471.2 R5952.2 R5954.2 U135.E1(VIN1_1) U135.E2(VIN1_2) U135.E3(VIN1_3) U135.E4(VIN1_4) U135.F1(VIN1_5) U135.F2(VIN1_6) U135.F3(VIN1_7) U135.F4(VIN1_8) U135.G1(VIN0_1) U135.G2(VIN0_2) U135.G3(VIN0_3) U135.G4(VIN0_4) U135.H1(VIN0_5) U135.H2(VIN0_6) U135.H3(VIN0_7) U135.H4(VIN0_8)
INTVCC6: C1332.1 R942.2 R946.2 R950.2 U71.20(INTVCC)
IO_1p8V: C7442.2 C7571.2 C7723.2 TP982.1 U117.A1(VOUT1_1) U117.A7(VOUT2_1) U117.B1(VOUT1_2) U117.B7(VOUT2_2) U117.F1(VOUT4_1) U117.F7(VOUT3_1) U117.G1(VOUT4_2) U117.G7(VOUT3_2) ; also on sheet 35 36 39 43 44 46 75 77
IO_1p8V_AGND: R6287.1 ST20.1
IO_1p8V_EN: R6167.1 ; also on sheet 51
IO_1p8V_PG: R6145.1 U117.D2(PGOOD1) ; also on sheet 50
LTM_INTVCC1: C7760.2 R6077.1 U117.C4(INTVCC) U117.C7(FB2) U117.E1(FB4) U117.E7(FB3)
LTM_PMBUS_ALERTn: R5937.2 R6163.2 U135.H11(~{ALERT}) ; also on sheet 59
LTM_SCL: J13.1 R621.2 R6289.2 U135.J12(SCL) U136.E4(SCL) ; also on sheet 59
LTM_SDA: J13.2 R622.2 R6290.2 U135.H10(SDA) U136.D4(SDA) ; also on sheet 59
MAIN_I2C_SCL: R621.1 ; also on sheet 43 44 46 77
MAIN_I2C_SDA: R622.1 ; also on sheet 43 44 46 77
PHMD6: R950.1 R953.2 U71.28(PHMODE)
VOSNS0_0P8V: R5925.2 U136.D7(VOSNS0+) U136.H7(VOSNS1)
N45051576: C1327.1 U71.25(TRACK/SS)
N45051609: C1328.2 R943.1 U71.24(ITH)
N45051685: R944.1 U71.27(RT)
N45051689: C1330.1 R945.2 R947.1 U71.23(FB)
N45051693: C1330.2 R945.1 R952.2
N45051842: TP18.1 U71.1(CLKOUT)
N45051844: R947.2 R951.2 U71.22(VOUTM)
N45052102: L22.1 U71.9(SW1) U71.10(SW2) U71.11(SW3) U71.12(SW4) U71.13(SW5) U71.14(SW6)
N47819054: TP1001.1(TP) U135.D12(VDD25)
N47819056: TP1002.1(TP) U135.E8(VDD33)
N47819060: C7464.2 R5952.1 U135.K1(IIN-)
N47819062: C7464.1 R5953.1 U135.J1(IIN+)
N47819276: R5949.2 U135.F12(ASEL)
N47819301: R5955.2 U135.D1(SVIN)
N47819873: U135.J8(TSNS0B) U135.J11(TSNS0A)
N47819899: U135.D8(TSNS1B) U135.J10(TSNS1A)
N47819921: R768.1 U135.E11(VOUT0_CFG) U135.E12(VOUT1_CFG)
N47819951: R5950.2 U135.C12(VTRIM0_CFG) U135.E10(VTRIM1_CFG)
N47819992: R6165.1 R6283.1 R6284.2 U135.F11(RUN1) U135.G12(RUN0)
N47820049: R6169.2 U135.F8(EXTVCC)
N47820094: R6170.2 U135.E9(FSWPH_CFG)
N47820137: C7461.1 U135.D10(COMP1A) U135.J9(COMP0A)
N47820145: R5956.2 U135.G11(~{FAULT1})
N47820149: C7462.1 U135.C10(COMP1B) U135.H9(COMP0B)
N47820157: R5957.2 U135.H12(~{FAULT0})
N47820167: R5958.2 U135.D11(SHARE_CLK)
N47820169: R5959.2 U135.K12(SYNC)
N47820215: R5948.1 U135.C11(WP)
N47828123: U136.J3(TSNS1A) U136.K3(TSNS1B)
N47828262: R5926.2 U136.J6(COMP1B)
N47828572: R5927.1 U136.F7(INTVCC1) U136.G7(INTVCC2)
N47828706: R5929.1 U136.E5(SYNC)
N47828708: R5930.1 U136.H5(SHARE_CLK)
N47828718: R5940.1 R5941.2 R6147.1 U136.F3(RUN0) U136.F4(RUN1)
N47828739: R5934.1 R5937.1 U136.E3(~{ALERT})
N47828768: D18.2(A) R5936.1 U136.E2(~{GPIO0})
N47828772: U136.C3(TSNS0_1) U136.D3(TSNS0_2)
N47828796: R5938.2 U136.K4(WP)
N47828848: TP1007.1 U136.J4(VDD25)
N47828909: R5944.2 U136.G2(ASEL)
N47828945: R5945.1 U136.H2(FSWPHCFG)
N47828991: R5946.2 U136.G3(VOUT0CFG) U136.G4(VOUT1CFG)
N47829001: R5947.2 U136.H3(VTRIM0CFG) U136.H4(VTRIM1CFG)
N47990323: R6166.1 R6167.2 R6168.1 U117.C3(RUN1) U117.C5(RUN2) U117.E3(RUN4) U117.E5(RUN3)
N48002409: R5928.2 R6056.2 U136.F9(SVIN)
N48273834: C7717.2 R6013.1 U114.A7(FB1) U114.D7(FB2) U114.G7(FB3) U114.J7(FB4)
N48273885: C7720.1 U114.B7(COMP1) U114.E7(COMP2) U114.H7(COMP3) U114.L7(COMP4)
N48273889: U114.B6(MODE1) U114.C4(INTVCC1)
N48273893: C7625.2 U114.A6(TRACK/SS1) U114.D6(TRACK/SS2) U114.G6(TRACK/SS3) U114.K6(TRACK/SS4)
N48273968: U114.E6(MODE2) U114.F4(INTVCC2)
N48274048: U114.H6(MODE3) U114.J4(INTVCC3)
N48274138: U114.K5(INTVCC4) U114.L6(MODE4)
N48274174: R6013.2 R6095.1
N48274294: R6096.1 U114.F3(TEMP)
N48495332: R6077.2 R6078.2 U117.E4(MODE/SYNC)
N48810027: R5931.1 U136.F2(~{GPIO1})
N48818862: C7660.1 R6154.2
N48819944: R5939.2 U136.D6(COMP0B)
N48819947: R5939.1 R6158.2 U136.E6(COMP0A)
N49540456: TP29.1(TP) U136.J5(VDD33)
N49541279: R6202.2 U136.E7(VOSNS0-)
N49664632: C7723.1 R2794.1 U117.C1(FB1)
N50651261: C1329.1 R943.2
N51024969: R2794.2 R6287.2

Not connected (* = marked no-connect by the designer): U71 21(M/S)*; U114 C2(PGOOD2)* C7(CLKIN)* F2(PGOOD3)* J2(PGOOD4)* J3(CLKOUT)*; U117 D1(PGOOD4)* D6(PGOOD2)* D7(PGOOD3)*; U135 A1(SW1_1)* A2(SW1_2)* B2(SW1_3)* L2(SW0_1)* M1(SW0_2)* M2(SW0_3)*; U136 B8(SW0)* D8(VORB0+)* E8(VORB0-)* J7(VORB1)* L8(SW1)*

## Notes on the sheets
sheet 63
- PWR - VCC_HSSI_GXR
- PMBus Address = 42h
- 50A
- Remote sense at FPGA
- LTM Dongle
- AGND
- PGND
sheet 64
- Power - VCCH
- Fswitch:
  1MHz
- 0.8V
sheet 65
- PWR - VCC_HSSI_GXF, VCCPLLDIG_SDM
- 0.8V @ 20A
- VIN  : 4.5V to 17V
- VOUT : 0.8V
- Tj   : -40 C TO 125 C
- ILOAD : 20A
- I2C ADDR = 46h
- (Top Side 30mil pad,
  No Via)
- FSW  : 575KHz
- NOTE: U136  Default configured for LTM4686EV-1 uModule
  If Changing to LTM4686EV
  Unmount R6056,R5927. Mount R5928
- 0.8V
- AGND
- PGND
- Place filter close to FPGA
sheet 66
- PWR - 1p8V
- VIN  : 4V to 20V
- VOUT : 1V8
- RFB : {( 60.4K/4)/(VOUT/0.6)-1)}
- RFB : 7.5K
- FSW  : 1.2 MHz
- Tj   : -40 C TO 125 C
- CURRENT : 12A
- AGND
- PGND
sheet 67
- PWR - IO_1p8V  for VCCIO_SDM, VCCIO_HPS, VCCBAT
- Connect the input
  cap to the GND plane
  through multiple vias.
  (see the Gerber files)
- 1.8V
- Connect the output
  cap to the GND plane
  through multiple vias
- AGND
